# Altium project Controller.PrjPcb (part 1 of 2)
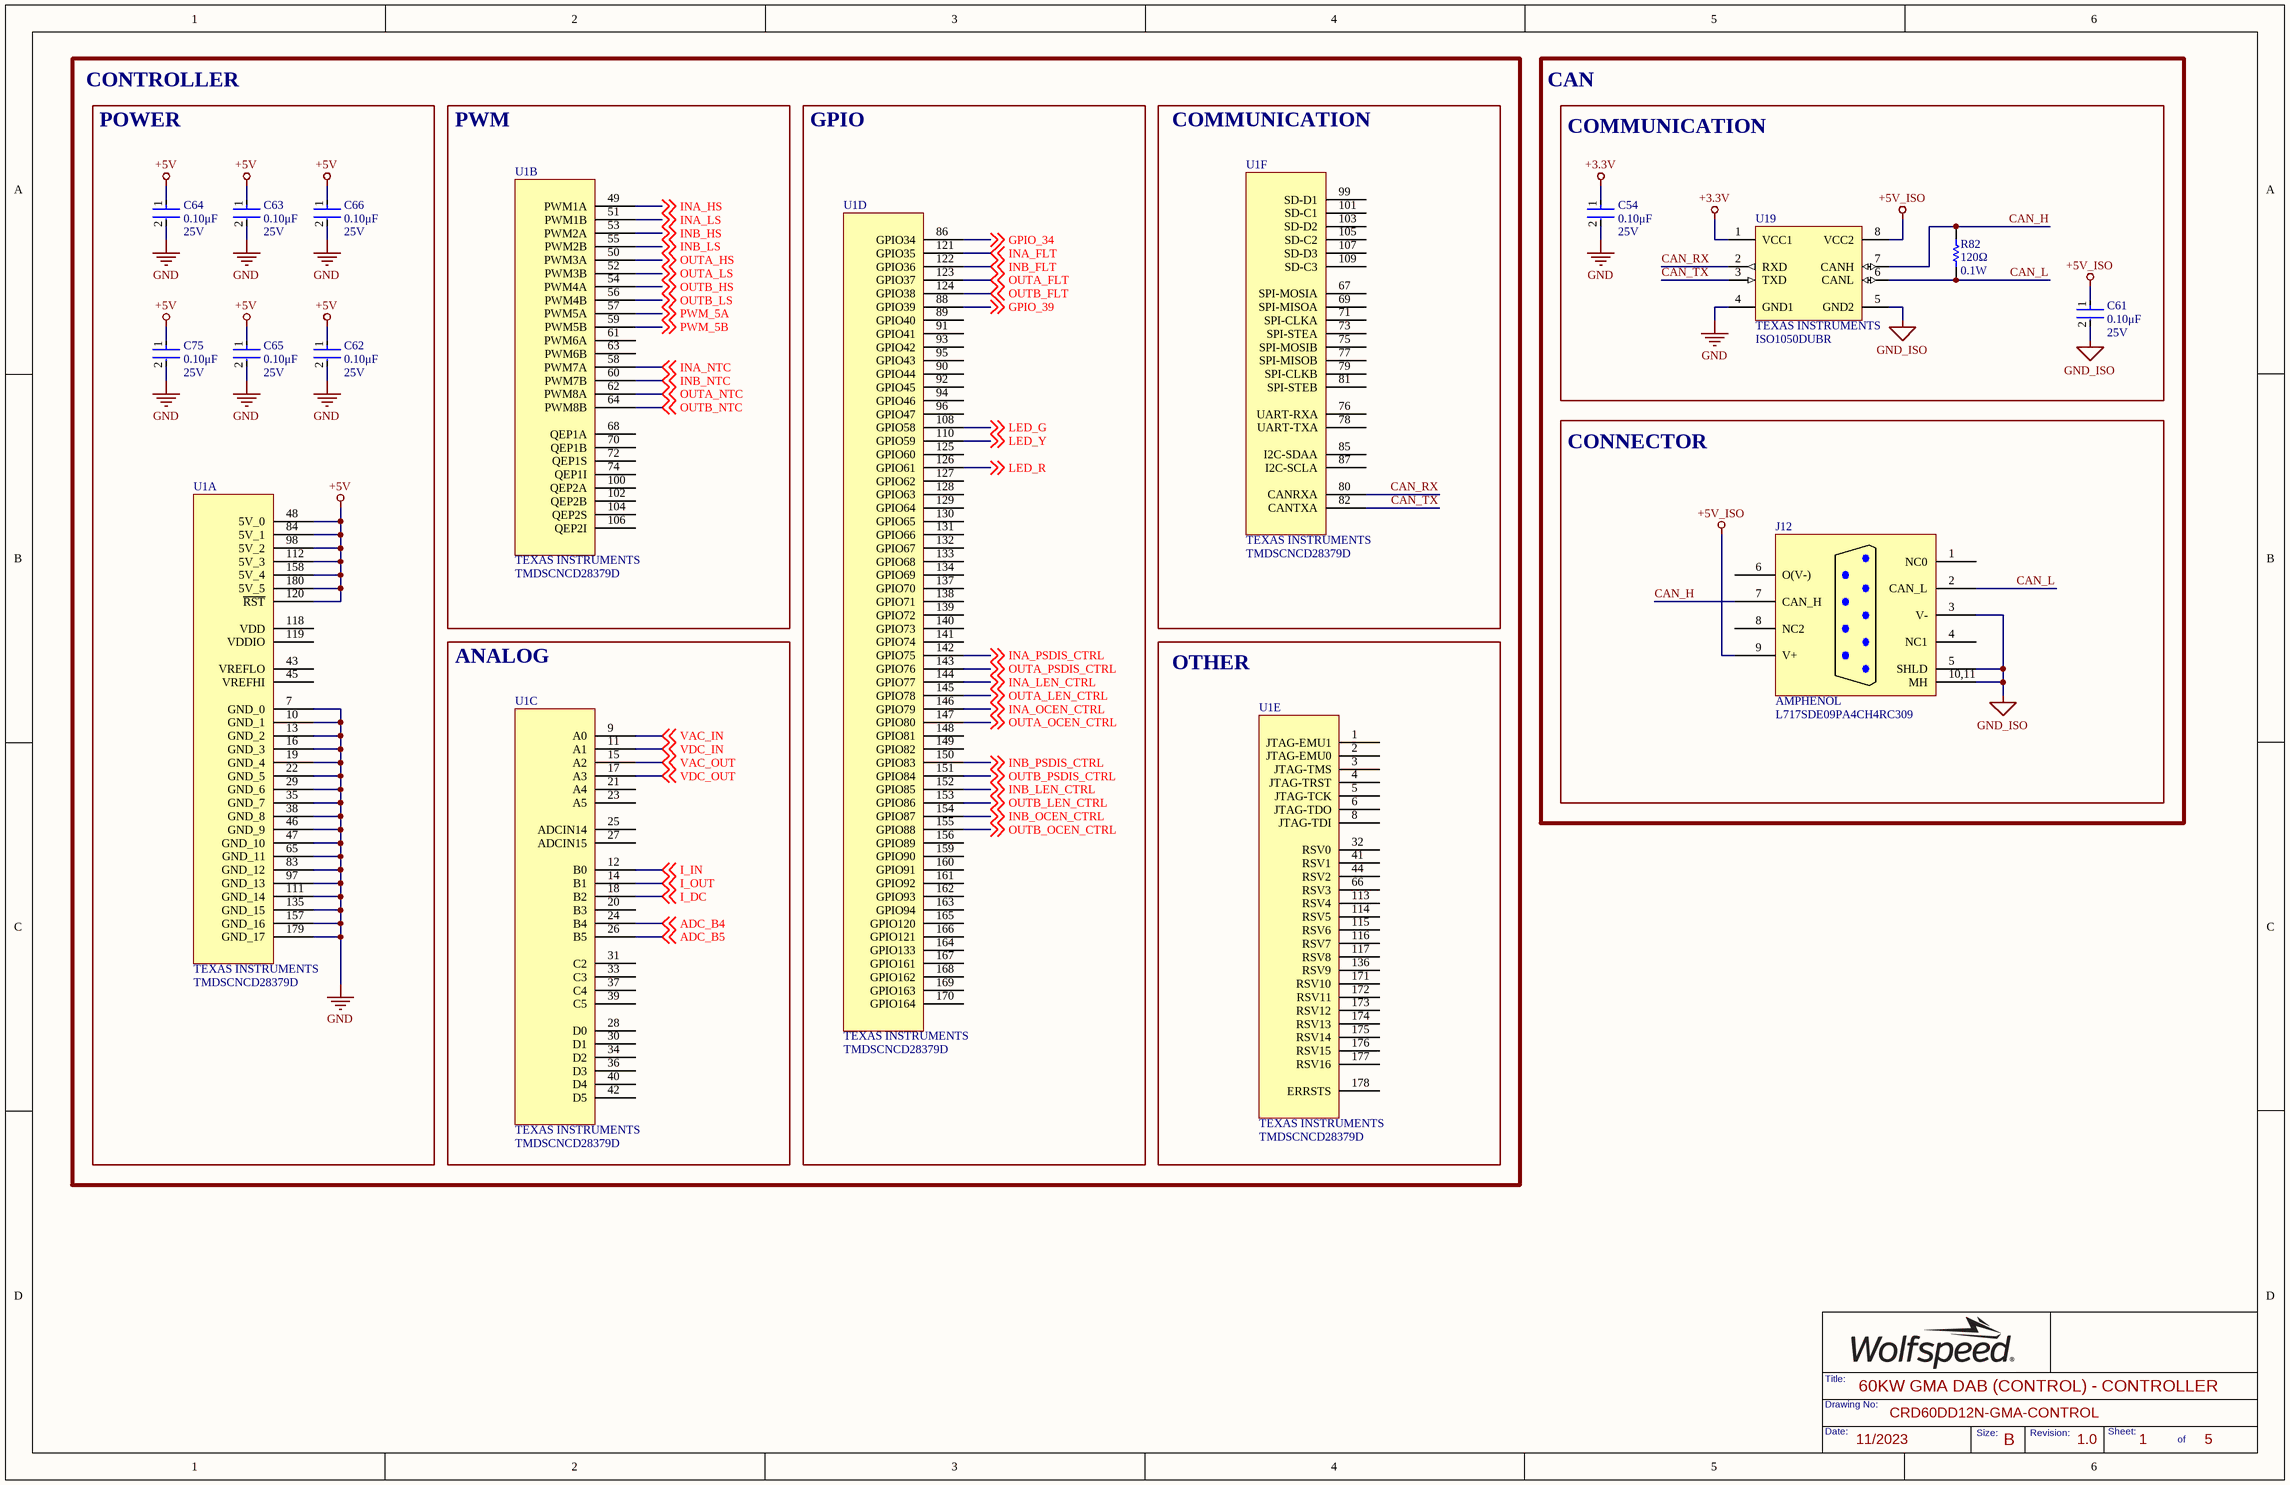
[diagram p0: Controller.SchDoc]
5 sheets, 303 parts. Net scope: global (net labels, ports and power ports of the same name join across sheets).
Board file: Controller.PcbDoc
Sheets:
  Controller.SchDoc
  Voltage Sense.SchDoc
  Gate Drivers.SchDoc
  Current Sense.SchDoc
  Auxiliary Power.SchDoc

## Sheet Controller.SchDoc: 60KW GMA DAB (CONTROL) - CONTROLLER
size 431 x 279 mm; Date: 11/2023; DocumentNumber: CRD60DD12N-GMA-CONTROL; Revision: 1.0; SheetNumber: 1; SheetTotal: 5; SheetSize: B

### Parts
C54  Voltage Rating: 25V  Capacitance: 0.10μF  [FP-C0603C-CF-IPC_B]  (hidden comment: C0603C104K3RACTU)
C61  Voltage Rating: 25V  Capacitance: 0.10μF  [FP-C0603C-CF-IPC_B]  (hidden comment: C0603C104K3RACTU)
C62  Voltage Rating: 25V  Capacitance: 0.10μF  [FP-C0603C-CF-IPC_B]  (hidden comment: C0603C104K3RACTU)
C63  Voltage Rating: 25V  Capacitance: 0.10μF  [FP-C0603C-CF-IPC_B]  (hidden comment: C0603C104K3RACTU)
C64  Voltage Rating: 25V  Capacitance: 0.10μF  [FP-C0603C-CF-IPC_B]  (hidden comment: C0603C104K3RACTU)
C65  Voltage Rating: 25V  Capacitance: 0.10μF  [FP-C0603C-CF-IPC_B]  (hidden comment: C0603C104K3RACTU)
C66  Voltage Rating: 25V  Capacitance: 0.10μF  [FP-C0603C-CF-IPC_B]  (hidden comment: C0603C104K3RACTU)
C75  Voltage Rating: 25V  Capacitance: 0.10μF  [FP-C0603C-CF-IPC_B]  (hidden comment: C0603C104K3RACTU)
J12  Manufacturer: AMPHENOL  [L717SDE09PA4CH4RC309]  (hidden comment: L717SDE09PA4CH4RC309)
R82  Resistance: 120Ω  Max Power Dissipation: 0.1W  [FP-MCR03-IPC_B]  (hidden comment: RC0603JR-07120RL)
U1  Manufacturer: TEXAS INSTRUMENTS  [TMDSCNCD28379D]  (hidden comment: TMDSCNCD28379D)  (parts A,B,C,D,E,F of 6)
U19  ISO1050DUBR  Manufacturer Print: TEXAS INSTRUMENTS  [DUB0008A_M]

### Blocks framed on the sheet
POWER: C62-C66 C75 U1
PWM: U1
GPIO: U1
COMMUNICATION: U1
COMMUNICATION: C54 C61 R82 U19
CONNECTOR: J12
ANALOG: U1
OTHER: U1

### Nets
+3.3V: C54.1 U19.1(VCC1)
+5V: C62.1 C63.1 C64.1 C65.1 C66.1 C75.1 U1.48(5V_0) U1.84(5V_1) U1.98(5V_2) U1.112(5V_3) U1.120(~{RST}) U1.158(5V_4) U1.180(5V_5)
+5V_ISO: C61.1 J12.9(V+) U19.8(VCC2)
GND: C54.2 C62.2 C63.2 C64.2 C65.2 C66.2 C75.2 U1.7(GND_0) U1.10(GND_1) U1.13(GND_2) U1.16(GND_3) U1.19(GND_4) U1.22(GND_5) U1.29(GND_6) U1.35(GND_7) U1.38(GND_8) U1.46(GND_9) U1.47(GND_10) U1.65(GND_11) U1.83(GND_12) U1.97(GND_13) U1.111(GND_14) U1.135(GND_15) U1.157(GND_16) U1.179(GND_17) U19.4(GND1)
GND_ISO: C61.2 J12.3(V-) J12.5(SHLD) J12.10,11(MH) U19.5(GND2)
ADC_B4: U1.24(B4) ; off-sheet ADC_B4
ADC_B5: U1.26(B5) ; off-sheet ADC_B5
CAN_H: J12.7(CAN_H) R82.2 U19.7(CANH)
CAN_L: J12.2(CAN_L) R82.1 U19.6(CANL)
CAN_RX: U1.80(CANRXA) U19.2(RXD)
CAN_TX: U1.82(CANTXA) U19.3(TXD)
GPIO_34: U1.86(GPIO34) ; off-sheet GPIO_34
GPIO_39: U1.88(GPIO39) ; off-sheet GPIO_39
I_DC: U1.18(B2) ; off-sheet I_DC
I_IN: U1.12(B0) ; off-sheet I_IN
I_OUT: U1.14(B1) ; off-sheet I_OUT
INA_FLT: U1.121(GPIO35) ; off-sheet INA_FLT
INA_HS: U1.49(PWM1A) ; off-sheet INA_HS
INA_LEN_CTRL: U1.144(GPIO77) ; off-sheet INA_LEN_CTRL
INA_LS: U1.51(PWM1B) ; off-sheet INA_LS
INA_NTC: U1.58(PWM7A) ; off-sheet INA_NTC
INA_OCEN_CTRL: U1.146(GPIO79) ; off-sheet INA_OCEN_CTRL
INA_PSDIS_CTRL: U1.142(GPIO75) ; off-sheet INA_PSDIS_CTRL
INB_FLT: U1.122(GPIO36) ; off-sheet INB_FLT
INB_HS: U1.53(PWM2A) ; off-sheet INB_HS
INB_LEN_CTRL: U1.152(GPIO85) ; off-sheet INB_LEN_CTRL
INB_LS: U1.55(PWM2B) ; off-sheet INB_LS
INB_NTC: U1.60(PWM7B) ; off-sheet INB_NTC
INB_OCEN_CTRL: U1.154(GPIO87) ; off-sheet INB_OCEN_CTRL
INB_PSDIS_CTRL: U1.150(GPIO83) ; off-sheet INB_PSDIS_CTRL
LED_G: U1.108(GPIO58) ; off-sheet LED_G
LED_R: U1.126(GPIO61) ; off-sheet LED_R
LED_Y: U1.110(GPIO59) ; off-sheet LED_Y
OUTA_FLT: U1.123(GPIO37) ; off-sheet OUTA_FLT
OUTA_HS: U1.50(PWM3A) ; off-sheet OUTA_HS
OUTA_LEN_CTRL: U1.145(GPIO78) ; off-sheet OUTA_LEN_CTRL
OUTA_LS: U1.52(PWM3B) ; off-sheet OUTA_LS
OUTA_NTC: U1.62(PWM8A) ; off-sheet OUTA_NTC
OUTA_OCEN_CTRL: U1.147(GPIO80) ; off-sheet OUTA_OCEN_CTRL
OUTA_PSDIS_CTRL: U1.143(GPIO76) ; off-sheet OUTA_PSDIS_CTRL
OUTB_FLT: U1.124(GPIO38) ; off-sheet OUTB_FLT
OUTB_HS: U1.54(PWM4A) ; off-sheet OUTB_HS
OUTB_LEN_CTRL: U1.153(GPIO86) ; off-sheet OUTB_LEN_CTRL
OUTB_LS: U1.56(PWM4B) ; off-sheet OUTB_LS
OUTB_NTC: U1.64(PWM8B) ; off-sheet OUTB_NTC
OUTB_OCEN_CTRL: U1.155(GPIO88) ; off-sheet OUTB_OCEN_CTRL
OUTB_PSDIS_CTRL: U1.151(GPIO84) ; off-sheet OUTB_PSDIS_CTRL
PWM_5A: U1.57(PWM5A) ; off-sheet PWM_5A
PWM_5B: U1.59(PWM5B) ; off-sheet PWM_5B
VAC_IN: U1.9(A0) ; off-sheet VAC_IN
VAC_OUT: U1.15(A2) ; off-sheet VAC_OUT
VDC_IN: U1.11(A1) ; off-sheet VDC_IN
VDC_OUT: U1.17(A3) ; off-sheet VDC_OUT

Not connected (* = marked no-connect by the designer): J12 1(NC0) 4(NC1) 6(O(V-)) 8(NC2); U1 1(JTAG-EMU1) 2(JTAG-EMU0) 3(JTAG-TMS) 4(JTAG-TRST) 5(JTAG-TCK) 6(JTAG-TDO) 8(JTAG-TDI) 20(B3) 21(A4) 23(A5) 25(ADCIN14) 27(ADCIN15) 28(D0) 30(D1) 31(C2) 32(RSV0) 33(C3) 34(D2) 36(D3) 37(C4) 39(C5) 40(D4) 41(RSV1) 42(D5) 43(VREFLO) 44(RSV2) 45(VREFHI) 61(PWM6A) 63(PWM6B) 66(RSV3) 67(SPI-MOSIA) 68(QEP1A) 69(SPI-MISOA) 70(QEP1B) 71(SPI-CLKA) 72(QEP1S) 73(SPI-STEA) 74(QEP1I) 75(SPI-MOSIB) 76(UART-RXA) 77(SPI-MISOB) 78(UART-TXA) 79(SPI-CLKB) 81(SPI-STEB) 85(I2C-SDAA) 87(I2C-SCLA) 89(GPIO40) 90(GPIO44) 91(GPIO41) 92(GPIO45) 93(GPIO42) 94(GPIO46) 95(GPIO43) 96(GPIO47) 99(SD-D1) 100(QEP2A) 101(SD-C1) 102(QEP2B) 103(SD-D2) 104(QEP2S) 105(SD-C2) 106(QEP2I) 107(SD-D3) 109(SD-C3) 113(RSV4) 114(RSV5) 115(RSV6) 116(RSV7) 117(RSV8) 118(VDD) 119(VDDIO) 125(GPIO60) 127(GPIO62) 128(GPIO63) 129(GPIO64) 130(GPIO65) 131(GPIO66) 132(GPIO67) 133(GPIO68) 134(GPIO69) 136(RSV9) 137(GPIO70) 138(GPIO71) 139(GPIO72) 140(GPIO73) 141(GPIO74) 148(GPIO81) 149(GPIO82) 156(GPIO89) 159(GPIO90) 160(GPIO91) 161(GPIO92) 162(GPIO93) 163(GPIO94) 164(GPIO133) 165(GPIO120) 166(GPIO121) 167(GPIO161) 168(GPIO162) 169(GPIO163) 170(GPIO164) 171(RSV10) 172(RSV11) 173(RSV12) 174(RSV13) 175(RSV14) 176(RSV15) 177(RSV16) 178(ERRSTS)

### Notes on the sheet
- CONTROLLER
- CAN

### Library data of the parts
C54 C61-C66 C75 = CMP-2006-03057-2: CAP CER 0.1UF 25V X7R 0603; Manufacturer: KEMET; Value: 0.10μF; Material: Ceramic; Tolerance: 0.1; Temperature Coefficient: 30ppm/°C; Automotive Grade: Grade 1
J12 = L717SDE09PA4CH4RC309: CONN D-SUB PLUG 9POS R/A SLDR; Number of Terminals/Pins: 9; Connector Type: D-Sub,Plug; Voltage Rating: 250V; Current Rating: 5A; Number of Ports: 1; Pitch: 2.74mm
R82 = RC0603JR-07120RL: RES SMD 120 OHM 5% 1/10W 0603; Manufacturer: YAGEO; Voltage Rating (DC): 50V; Temperature Coefficient: 100ppm/°C; Power Rating: 100mW; Value: 120Ω
U1 = TMDSCNCD28379D: CONTROLCARD TMS320F28379D EVAL; Evaluation Kit: Yes
U19 = ISO1050DUBR: IC TXRX/ISO HALF 1/1 8SOP; Rating: Catalog; Eco-Plan: Green (RoHS & no Sb/Br); Isolated: Yes; Drivers Per Package: 1; SubFamily: CAN

## Sheet Voltage Sense.SchDoc: 60KW GMA DAB (CONTROL) - VOLTAGE SENSE
size 431 x 279 mm; Date: 11/2023; Revision: 1.0; SheetNumber: 2; SheetTotal: 5; SheetSize: B; DrawingNumber: CRD60DD12N-GMA-CONTROL
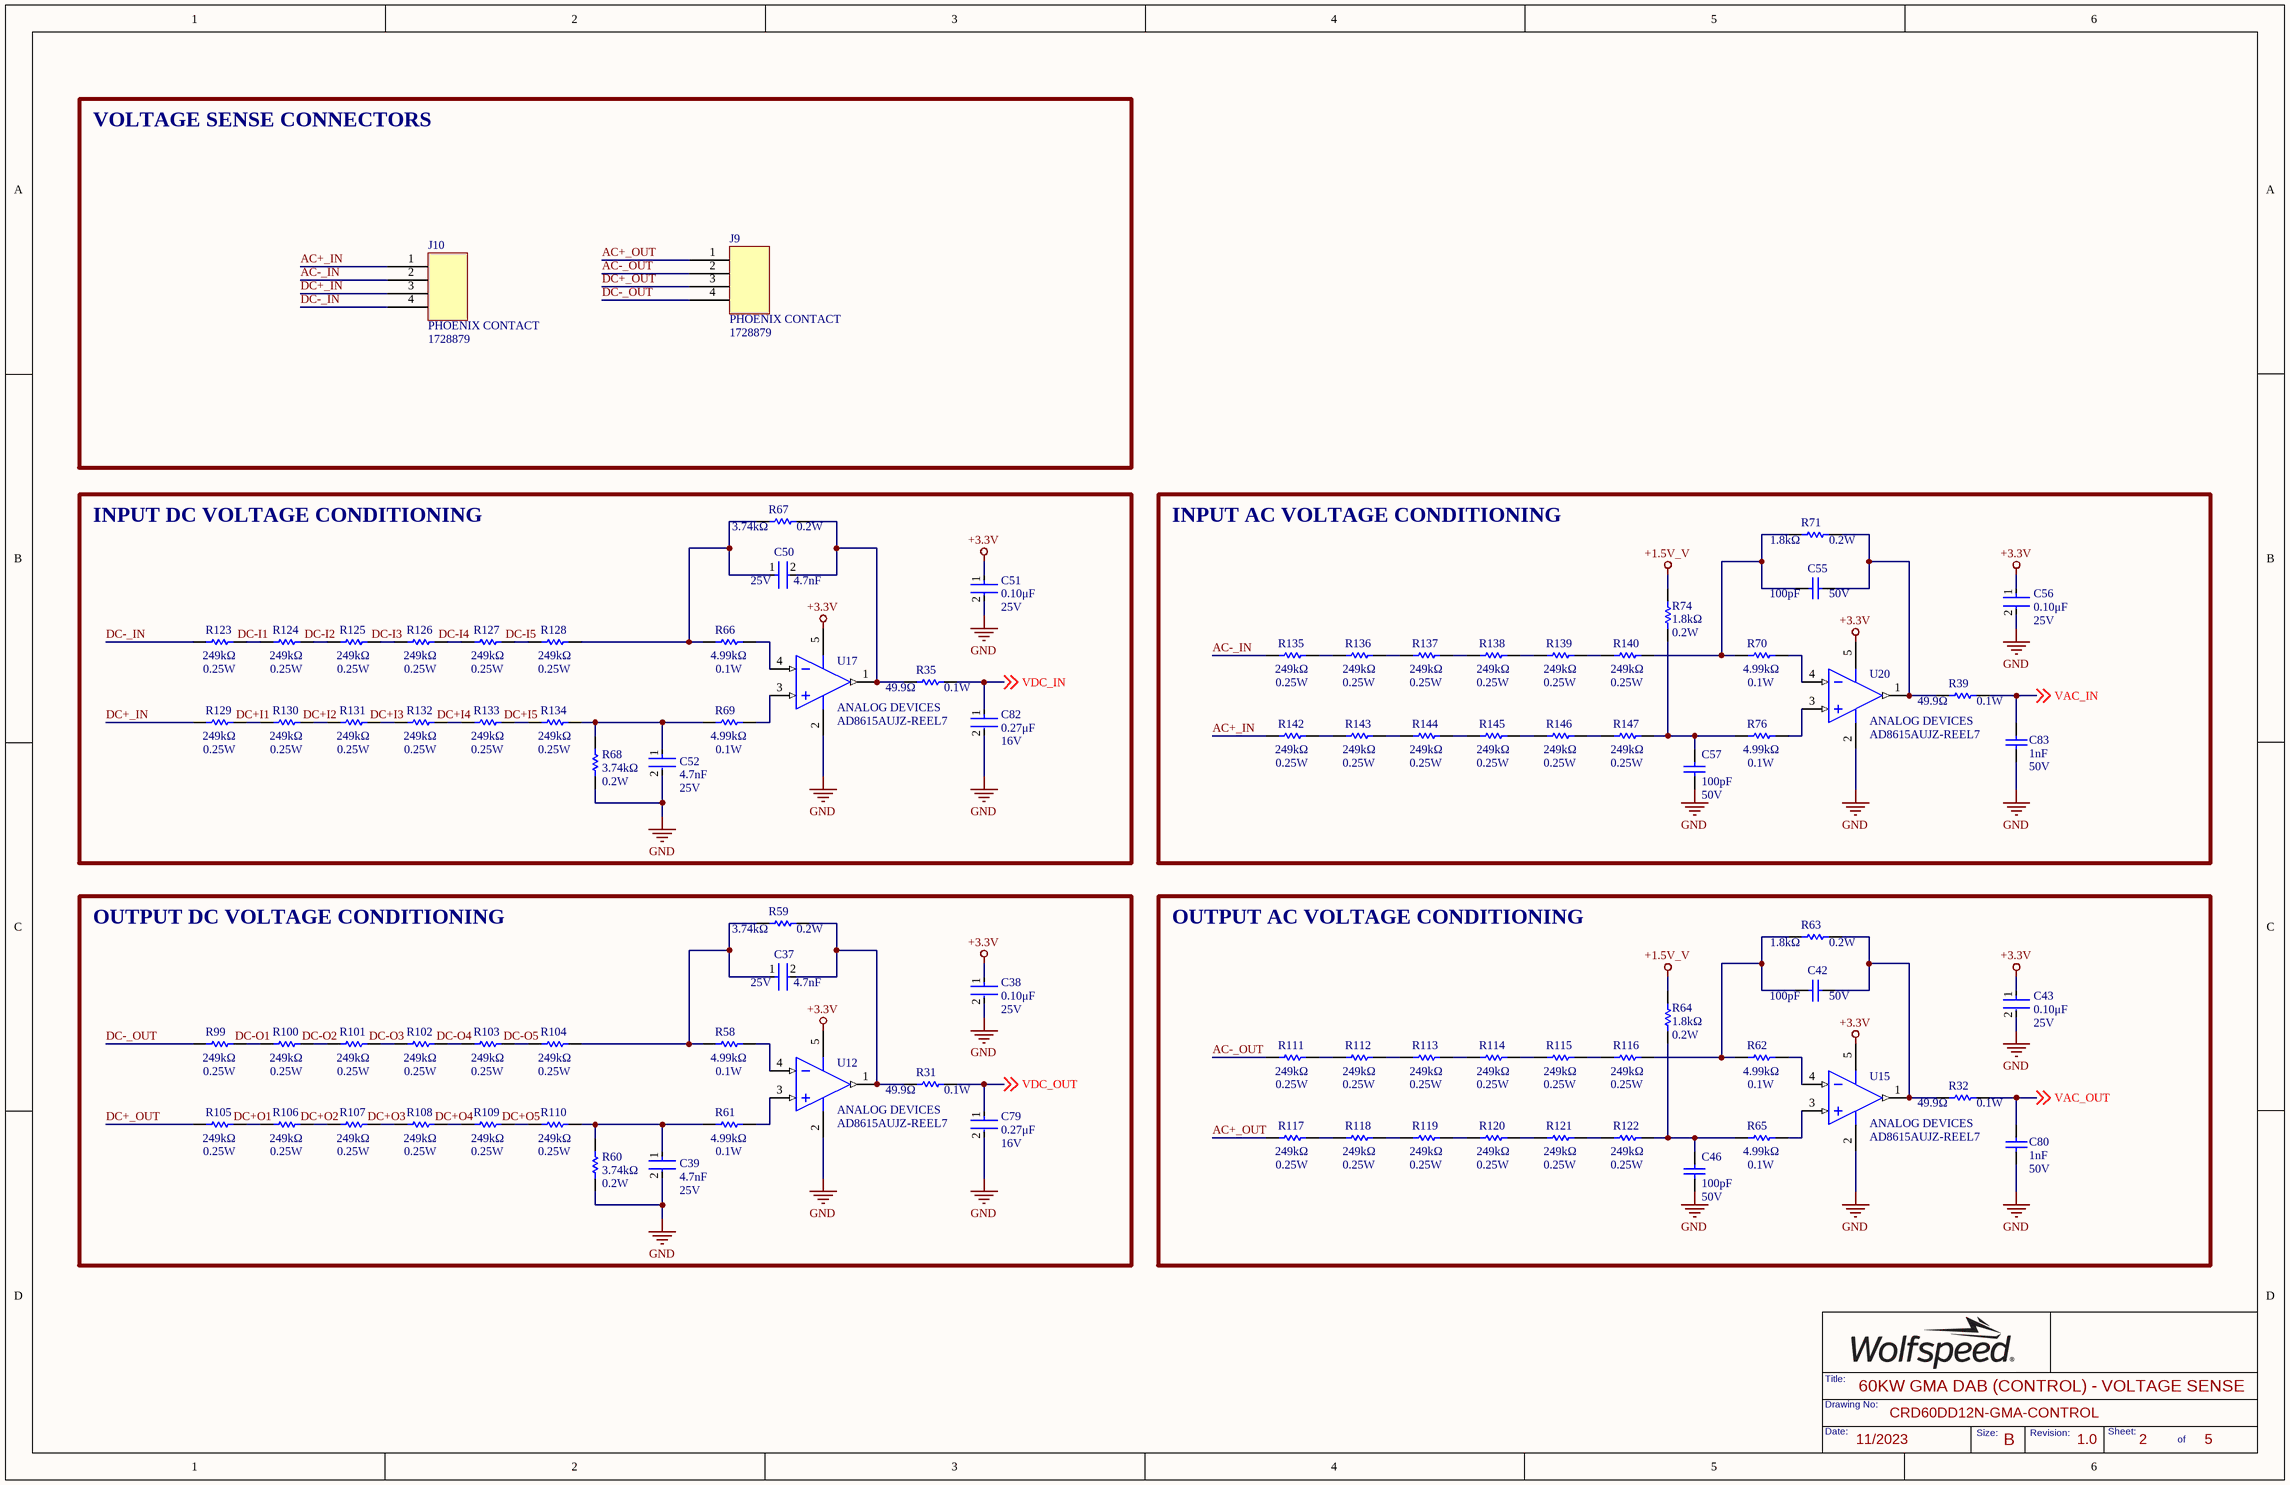
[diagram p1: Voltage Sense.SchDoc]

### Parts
C37  Voltage Rating: 25V  Capacitance: 4.7nF  [FP-C0603C-CF-IPC_B]  (hidden comment: C0603C472K3RAC7867)
C38  Voltage Rating: 25V  Capacitance: 0.10μF  [FP-C0603C-CF-IPC_B]  (hidden comment: C0603C104K3RACTU)
C39  Voltage Rating: 25V  Capacitance: 4.7nF  [FP-C0603C-CF-IPC_B]  (hidden comment: C0603C472K3RAC7867)
C42  value 100pF  Voltage Rating: 50V  [FP-C0603C-CF-IPC_B]  (hidden comment: CC0603KRX7R9BB101)
C43  Voltage Rating: 25V  Capacitance: 0.10μF  [FP-C0603C-CF-IPC_B]  (hidden comment: C0603C104K3RACTU)
C46  value 100pF  Voltage Rating: 50V  [FP-C0603C-CF-IPC_B]  (hidden comment: CC0603KRX7R9BB101)
C50  Voltage Rating: 25V  Capacitance: 4.7nF  [FP-C0603C-CF-IPC_B]  (hidden comment: C0603C472K3RAC7867)
C51  Voltage Rating: 25V  Capacitance: 0.10μF  [FP-C0603C-CF-IPC_B]  (hidden comment: C0603C104K3RACTU)
C52  Voltage Rating: 25V  Capacitance: 4.7nF  [FP-C0603C-CF-IPC_B]  (hidden comment: C0603C472K3RAC7867)
C55  value 100pF  Voltage Rating: 50V  [FP-C0603C-CF-IPC_B]  (hidden comment: CC0603KRX7R9BB101)
C56  Voltage Rating: 25V  Capacitance: 0.10μF  [FP-C0603C-CF-IPC_B]  (hidden comment: C0603C104K3RACTU)
C57  value 100pF  Voltage Rating: 50V  [FP-C0603C-CF-IPC_B]  (hidden comment: CC0603KRX7R9BB101)
C79  Voltage Rating (DC): 16V  Capacitance: 0.27μF  [FP-GCM188-0_1-IPC_A]  (hidden comment: GCM188R71C274KA37D)
C80  value 1nF  Voltage Rating: 50V  [FP-C0603C-CF-IPC_B]  (hidden comment: GRM1885C1H102GA01D)
C82  Voltage Rating (DC): 16V  Capacitance: 0.27μF  [FP-GCM188-0_1-IPC_A]  (hidden comment: GCM188R71C274KA37D)
C83  value 1nF  Voltage Rating: 50V  [FP-C0603C-CF-IPC_B]  (hidden comment: GRM1885C1H102GA01D)
J9  1728879  Manufacturer: PHOENIX CONTACT  [1728879]
J10  1728879  Manufacturer: PHOENIX CONTACT  [1728879]
R31  Resistance: 49.9Ω  Power Rating: 0.1W  [FP-MCR03-IPC_B]  (hidden comment: ERJ-3EKF49R9V)
R32  Resistance: 49.9Ω  Power Rating: 0.1W  [FP-MCR03-IPC_B]  (hidden comment: ERJ-3EKF49R9V)
R35  Resistance: 49.9Ω  Power Rating: 0.1W  [FP-MCR03-IPC_B]  (hidden comment: ERJ-3EKF49R9V)
R39  Resistance: 49.9Ω  Power Rating: 0.1W  [FP-MCR03-IPC_B]  (hidden comment: ERJ-3EKF49R9V)
R58  Power Rating: 0.1W  Resistance: 4.99kΩ  [FP-MCR03-IPC_B]  (hidden comment: RC0603FR-074K99L)
R59  Max Power Dissipation: 0.2W  Resistance: 3.74kΩ  [FP-MCR03-IPC_B]  (hidden comment: ERJ-PB3B3741V)
R60  Max Power Dissipation: 0.2W  Resistance: 3.74kΩ  [FP-MCR03-IPC_B]  (hidden comment: ERJ-PB3B3741V)
R61  Power Rating: 0.1W  Resistance: 4.99kΩ  [FP-MCR03-IPC_B]  (hidden comment: RC0603FR-074K99L)
R62  Power Rating: 0.1W  Resistance: 4.99kΩ  [FP-MCR03-IPC_B]  (hidden comment: RC0603FR-074K99L)
R63  Resistance: 1.8kΩ  Max Power Dissipation: 0.2W  [FP-MCR03-IPC_B]  (hidden comment: ERJ-PB3B1801V)
R64  Resistance: 1.8kΩ  Max Power Dissipation: 0.2W  [FP-MCR03-IPC_B]  (hidden comment: ERJ-PB3B1801V)
R65  Power Rating: 0.1W  Resistance: 4.99kΩ  [FP-MCR03-IPC_B]  (hidden comment: RC0603FR-074K99L)
R66  Power Rating: 0.1W  Resistance: 4.99kΩ  [FP-MCR03-IPC_B]  (hidden comment: RC0603FR-074K99L)
R67  Max Power Dissipation: 0.2W  Resistance: 3.74kΩ  [FP-MCR03-IPC_B]  (hidden comment: ERJ-PB3B3741V)
R68  Max Power Dissipation: 0.2W  Resistance: 3.74kΩ  [FP-MCR03-IPC_B]  (hidden comment: ERJ-PB3B3741V)
R69  Power Rating: 0.1W  Resistance: 4.99kΩ  [FP-MCR03-IPC_B]  (hidden comment: RC0603FR-074K99L)
R70  Power Rating: 0.1W  Resistance: 4.99kΩ  [FP-MCR03-IPC_B]  (hidden comment: RC0603FR-074K99L)
R71  Resistance: 1.8kΩ  Max Power Dissipation: 0.2W  [FP-MCR03-IPC_B]  (hidden comment: ERJ-PB3B1801V)
R74  Resistance: 1.8kΩ  Max Power Dissipation: 0.2W  [FP-MCR03-IPC_B]  (hidden comment: ERJ-PB3B1801V)
R76  Power Rating: 0.1W  Resistance: 4.99kΩ  [FP-MCR03-IPC_B]  (hidden comment: RC0603FR-074K99L)
R99  Resistance: 249kΩ  Power: 0.25W  [RESC3216X65X50NL15T25]  (hidden comment: TNPW1206249KBEEA)
R100  Resistance: 249kΩ  Power: 0.25W  [RESC3216X65X50NL15T25]  (hidden comment: TNPW1206249KBEEA)
R101  Resistance: 249kΩ  Power: 0.25W  [RESC3216X65X50NL15T25]  (hidden comment: TNPW1206249KBEEA)
R102  Resistance: 249kΩ  Power: 0.25W  [RESC3216X65X50NL15T25]  (hidden comment: TNPW1206249KBEEA)
R103  Resistance: 249kΩ  Power: 0.25W  [RESC3216X65X50NL15T25]  (hidden comment: TNPW1206249KBEEA)
R104  Resistance: 249kΩ  Power: 0.25W  [RESC3216X65X50NL15T25]  (hidden comment: TNPW1206249KBEEA)
R105  Resistance: 249kΩ  Power: 0.25W  [RESC3216X65X50NL15T25]  (hidden comment: TNPW1206249KBEEA)
R106  Resistance: 249kΩ  Power: 0.25W  [RESC3216X65X50NL15T25]  (hidden comment: TNPW1206249KBEEA)
R107  Resistance: 249kΩ  Power: 0.25W  [RESC3216X65X50NL15T25]  (hidden comment: TNPW1206249KBEEA)
R108  Resistance: 249kΩ  Power: 0.25W  [RESC3216X65X50NL15T25]  (hidden comment: TNPW1206249KBEEA)
R109  Resistance: 249kΩ  Power: 0.25W  [RESC3216X65X50NL15T25]  (hidden comment: TNPW1206249KBEEA)
R110  Resistance: 249kΩ  Power: 0.25W  [RESC3216X65X50NL15T25]  (hidden comment: TNPW1206249KBEEA)
R111  Resistance: 249kΩ  Power: 0.25W  [RESC3216X65X50NL15T25]  (hidden comment: TNPW1206249KBEEA)
R112  Resistance: 249kΩ  Power: 0.25W  [RESC3216X65X50NL15T25]  (hidden comment: TNPW1206249KBEEA)
R113  Resistance: 249kΩ  Power: 0.25W  [RESC3216X65X50NL15T25]  (hidden comment: TNPW1206249KBEEA)
R114  Resistance: 249kΩ  Power: 0.25W  [RESC3216X65X50NL15T25]  (hidden comment: TNPW1206249KBEEA)
R115  Resistance: 249kΩ  Power: 0.25W  [RESC3216X65X50NL15T25]  (hidden comment: TNPW1206249KBEEA)
R116  Resistance: 249kΩ  Power: 0.25W  [RESC3216X65X50NL15T25]  (hidden comment: TNPW1206249KBEEA)
R117  Resistance: 249kΩ  Power: 0.25W  [RESC3216X65X50NL15T25]  (hidden comment: TNPW1206249KBEEA)
R118  Resistance: 249kΩ  Power: 0.25W  [RESC3216X65X50NL15T25]  (hidden comment: TNPW1206249KBEEA)
R119  Resistance: 249kΩ  Power: 0.25W  [RESC3216X65X50NL15T25]  (hidden comment: TNPW1206249KBEEA)
R120  Resistance: 249kΩ  Power: 0.25W  [RESC3216X65X50NL15T25]  (hidden comment: TNPW1206249KBEEA)
R121  Resistance: 249kΩ  Power: 0.25W  [RESC3216X65X50NL15T25]  (hidden comment: TNPW1206249KBEEA)
R122  Resistance: 249kΩ  Power: 0.25W  [RESC3216X65X50NL15T25]  (hidden comment: TNPW1206249KBEEA)
R123  Resistance: 249kΩ  Power: 0.25W  [RESC3216X65X50NL15T25]  (hidden comment: TNPW1206249KBEEA)
R124  Resistance: 249kΩ  Power: 0.25W  [RESC3216X65X50NL15T25]  (hidden comment: TNPW1206249KBEEA)
R125  Resistance: 249kΩ  Power: 0.25W  [RESC3216X65X50NL15T25]  (hidden comment: TNPW1206249KBEEA)
R126  Resistance: 249kΩ  Power: 0.25W  [RESC3216X65X50NL15T25]  (hidden comment: TNPW1206249KBEEA)
R127  Resistance: 249kΩ  Power: 0.25W  [RESC3216X65X50NL15T25]  (hidden comment: TNPW1206249KBEEA)
R128  Resistance: 249kΩ  Power: 0.25W  [RESC3216X65X50NL15T25]  (hidden comment: TNPW1206249KBEEA)
R129  Resistance: 249kΩ  Power: 0.25W  [RESC3216X65X50NL15T25]  (hidden comment: TNPW1206249KBEEA)
R130  Resistance: 249kΩ  Power: 0.25W  [RESC3216X65X50NL15T25]  (hidden comment: TNPW1206249KBEEA)
R131  Resistance: 249kΩ  Power: 0.25W  [RESC3216X65X50NL15T25]  (hidden comment: TNPW1206249KBEEA)
R132  Resistance: 249kΩ  Power: 0.25W  [RESC3216X65X50NL15T25]  (hidden comment: TNPW1206249KBEEA)
R133  Resistance: 249kΩ  Power: 0.25W  [RESC3216X65X50NL15T25]  (hidden comment: TNPW1206249KBEEA)
R134  Resistance: 249kΩ  Power: 0.25W  [RESC3216X65X50NL15T25]  (hidden comment: TNPW1206249KBEEA)
R135  Resistance: 249kΩ  Power: 0.25W  [RESC3216X65X50NL15T25]  (hidden comment: TNPW1206249KBEEA)
R136  Resistance: 249kΩ  Power: 0.25W  [RESC3216X65X50NL15T25]  (hidden comment: TNPW1206249KBEEA)
R137  Resistance: 249kΩ  Power: 0.25W  [RESC3216X65X50NL15T25]  (hidden comment: TNPW1206249KBEEA)
R138  Resistance: 249kΩ  Power: 0.25W  [RESC3216X65X50NL15T25]  (hidden comment: TNPW1206249KBEEA)
R139  Resistance: 249kΩ  Power: 0.25W  [RESC3216X65X50NL15T25]  (hidden comment: TNPW1206249KBEEA)
R140  Resistance: 249kΩ  Power: 0.25W  [RESC3216X65X50NL15T25]  (hidden comment: TNPW1206249KBEEA)
R142  Resistance: 249kΩ  Power: 0.25W  [RESC3216X65X50NL15T25]  (hidden comment: TNPW1206249KBEEA)
R143  Resistance: 249kΩ  Power: 0.25W  [RESC3216X65X50NL15T25]  (hidden comment: TNPW1206249KBEEA)
R144  Resistance: 249kΩ  Power: 0.25W  [RESC3216X65X50NL15T25]  (hidden comment: TNPW1206249KBEEA)
R145  Resistance: 249kΩ  Power: 0.25W  [RESC3216X65X50NL15T25]  (hidden comment: TNPW1206249KBEEA)
R146  Resistance: 249kΩ  Power: 0.25W  [RESC3216X65X50NL15T25]  (hidden comment: TNPW1206249KBEEA)
R147  Resistance: 249kΩ  Power: 0.25W  [RESC3216X65X50NL15T25]  (hidden comment: TNPW1206249KBEEA)
U12  Manufacturer: ANALOG DEVICES  [ADI-UJ-5_M]  (hidden comment: AD8615AUJZ-REEL7)
U15  Manufacturer: ANALOG DEVICES  [ADI-UJ-5_M]  (hidden comment: AD8615AUJZ-REEL7)
U17  Manufacturer: ANALOG DEVICES  [ADI-UJ-5_M]  (hidden comment: AD8615AUJZ-REEL7)
U20  Manufacturer: ANALOG DEVICES  [ADI-UJ-5_M]  (hidden comment: AD8615AUJZ-REEL7)

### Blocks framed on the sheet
VOLTAGE SENSE CONNECTORS: J9 J10
INPUT DC VOLTAGE CONDITIONING: C50-C52 C82 R35 R66-R69 R123-R134 U17
INPUT AC VOLTAGE CONDITIONING: C55-C57 C83 R39 R70 R71 R74 R76 R135-R140 R142-R147 U20
OUTPUT DC VOLTAGE CONDITIONING: C37-C39 C79 R31 R58-R61 R99-R110 U12
OUTPUT AC VOLTAGE CONDITIONING: C42 C43 C46 C80 R32 R62-R65 R111-R122 U15

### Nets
+1.5V_V: R64.2 R74.2
+3.3V: C38.1 C43.1 C51.1 C56.1 U12.5(+V) U15.5(+V) U17.5(+V) U20.5(+V)
GND: C38.2 C39.2 C43.2 C46.2 C51.2 C52.2 C56.2 C57.2 C79.2 C80.2 C82.2 C83.2 R60.1 R68.1 U12.2(-V) U15.2(-V) U17.2(-V) U20.2(-V)
AC+_IN: J10.1 R142.1
AC+_OUT: J9.1 R117.1
AC-_IN: J10.2 R135.1
AC-_OUT: J9.2 R111.1
DC+_IN: J10.3 R129.1
DC+_OUT: J9.3 R105.1
DC+I1: R129.2 R130.1
DC+I2: R130.2 R131.1
DC+I3: R131.2 R132.1
DC+I4: R132.2 R133.1
DC+I5: R133.2 R134.1
DC+O1: R105.2 R106.1
DC+O2: R106.2 R107.1
DC+O3: R107.2 R108.1
DC+O4: R108.2 R109.1
DC+O5: R109.2 R110.1
DC-_IN: J10.4 R123.1
DC-_OUT: J9.4 R99.1
DC-I1: R123.2 R124.1
DC-I2: R124.2 R125.1
DC-I3: R125.2 R126.1
DC-I4: R126.2 R127.1
DC-I5: R127.2 R128.1
DC-O1: R99.2 R100.1
DC-O2: R100.2 R101.1
DC-O3: R101.2 R102.1
DC-O4: R102.2 R103.1
DC-O5: R103.2 R104.1
VAC_IN: C83.1 R39.2 ; off-sheet VAC_IN
VAC_OUT: C80.1 R32.2 ; off-sheet VAC_OUT
VDC_IN: C82.1 R35.2 ; off-sheet VDC_IN
VDC_OUT: C79.1 R31.2 ; off-sheet VDC_OUT
NetC37_1: C37.1 R58.1 R59.1 R104.2
NetC37_2: C37.2 R31.1 R59.2 U12.1(OUT)
NetC39_1: C39.1 R60.2 R61.1 R110.2
NetC42_1: C42.1 R62.1 R63.2 R116.2
NetC42_2: C42.2 R32.1 R63.1 U15.1(OUT)
NetC46_1: C46.1 R64.1 R65.1 R122.2
NetC50_1: C50.1 R66.1 R67.1 R128.2
NetC50_2: C50.2 R35.1 R67.2 U17.1(OUT)
NetC52_1: C52.1 R68.2 R69.1 R134.2
NetC55_1: C55.1 R70.1 R71.2 R140.2
NetC55_2: C55.2 R39.1 R71.1 U20.1(OUT)
NetC57_1: C57.1 R74.1 R76.1 R147.2
NetR58_2: R58.2 U12.4(-IN)
NetR61_2: R61.2 U12.3(+IN)
NetR62_2: R62.2 U15.4(-IN)
NetR65_2: R65.2 U15.3(+IN)
NetR66_2: R66.2 U17.4(-IN)
NetR69_2: R69.2 U17.3(+IN)
NetR70_2: R70.2 U20.4(-IN)
NetR76_2: R76.2 U20.3(+IN)
NetR111_2: R111.2 R112.1
NetR112_2: R112.2 R113.1
NetR113_2: R113.2 R114.1
NetR114_2: R114.2 R115.1
NetR115_2: R115.2 R116.1
NetR117_2: R117.2 R118.1
NetR118_2: R118.2 R119.1
NetR119_2: R119.2 R120.1
NetR120_2: R120.2 R121.1
NetR121_2: R121.2 R122.1
NetR135_2: R135.2 R136.1
NetR136_2: R136.2 R137.1
NetR137_2: R137.2 R138.1
NetR138_2: R138.2 R139.1
NetR139_2: R139.2 R140.1
NetR142_2: R142.2 R143.1
NetR143_2: R143.2 R144.1
NetR144_2: R144.2 R145.1
NetR145_2: R145.2 R146.1
NetR146_2: R146.2 R147.1

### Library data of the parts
C37 C39 C50 C52 = C0603C472K3RAC7867: CAP CER 4700PF 25V 10% X7R 0603; Manufacturer: KEMET; Manufacturer Part Number: C0603C472K3RACTU; Dielectric Material: Ceramic; Value: 4.7nF
C38 C43 C51 C56 = CMP-2006-03057-2: as C54 on sheet Controller
C42 C46 C55 C57 = CMP-001-00096-9: CAP CER 100PF 50V X7R 0603; Manufacturer: YAGEO; Tolerance: 10%; Capacitor Type: Ceramic
C79 C82 = CMP-06035-043171-1: CAP CER 0.27UF 16V X7R 0603; Manufacturer: MURATA; Tolerance: 10%; Value: 0.27μF
C80 C83 = CMP-001-00098-12: CAP CER 1000PF 50V C0G/NP0 0603; Manufacturer: KEMET; Manufacturer Part Number: C0603C102G5GAC7867; Capacitor Type: Ceramic; Tolerance: 2%; Temperature Coefficient: C0G
J9 J10 = 1728879: TERM BLOCK HDR 4POS 90DEG 7.62MM
R31 R32 R35 R39 = ERJ-3EKF49R9V: RES SMD 49.9 OHM 1% 1/10W 0603; Manufacturer: PANASONIC; Temperature Coefficient: 100ppm/°C; Voltage Rating: 75V; Max Power Dissipation: 100mW; Voltage Rating (DC): 50V; Working Voltage: 6V; Value: 49.9Ω
R58 R61 R62 R65 R66 R69 R70 R76 = RC0603FR-074K99L: RES 4.99K OHM 1% 1/10W 0603; Manufacturer: YAGEO; Voltage Rating: 75V; Temperature Coefficient: 100ppm/°C; Voltage Rating (DC): 50V; Value: 4.99kΩ
R59 R60 R67 R68 = ERJ-PB3B3741V: RES SMD 3.74K OHM 0.1% 1/5W 0603; Manufacturer: PANASONIC; Temperature Coefficient: 50ppm/°C; Value: 3.74kΩ
R63 R64 R71 R74 = ERJ-PB3B1801V: RES SMD 1.8K OHM 0.1% 1/5W 0603; Manufacturer: PANASONIC; Temperature Coefficient: 50ppm/°C; Value: 1.8kΩ
R99-R140 R142-R147 = CMP-2003-04604-1: RES 249K OHM 0.1% 1/4W 1206; Manufacturer: VISHAY DALE; Value: 249kΩ
U12 U15 U17 U20 = CMP-0384-02059-2: IC OPAMP GP 1 CIRCUIT TSOT23-5; Generic Part Number: AD8615; Iq/Amp: 1.7mA; V Span Max: 6V; Amplifiers Per Package: 1; Small Signal Bandwidth: 23MHz; Input Offset Voltage: 80uV; V Span Min: 2.7V; Slew Rate: 12V/us; Input Bias Current: 200fA

## Sheet Gate Drivers.SchDoc: 60KW GMA DAB (CONTROL) - GATE DRIVERS
size 431 x 279 mm; Date: 11/2023; Revision: 1.0; SheetNumber: 3; SheetTotal: 5; SheetSize: B; DrawingNumber: CRD60DD12N-GMA-CONTROL
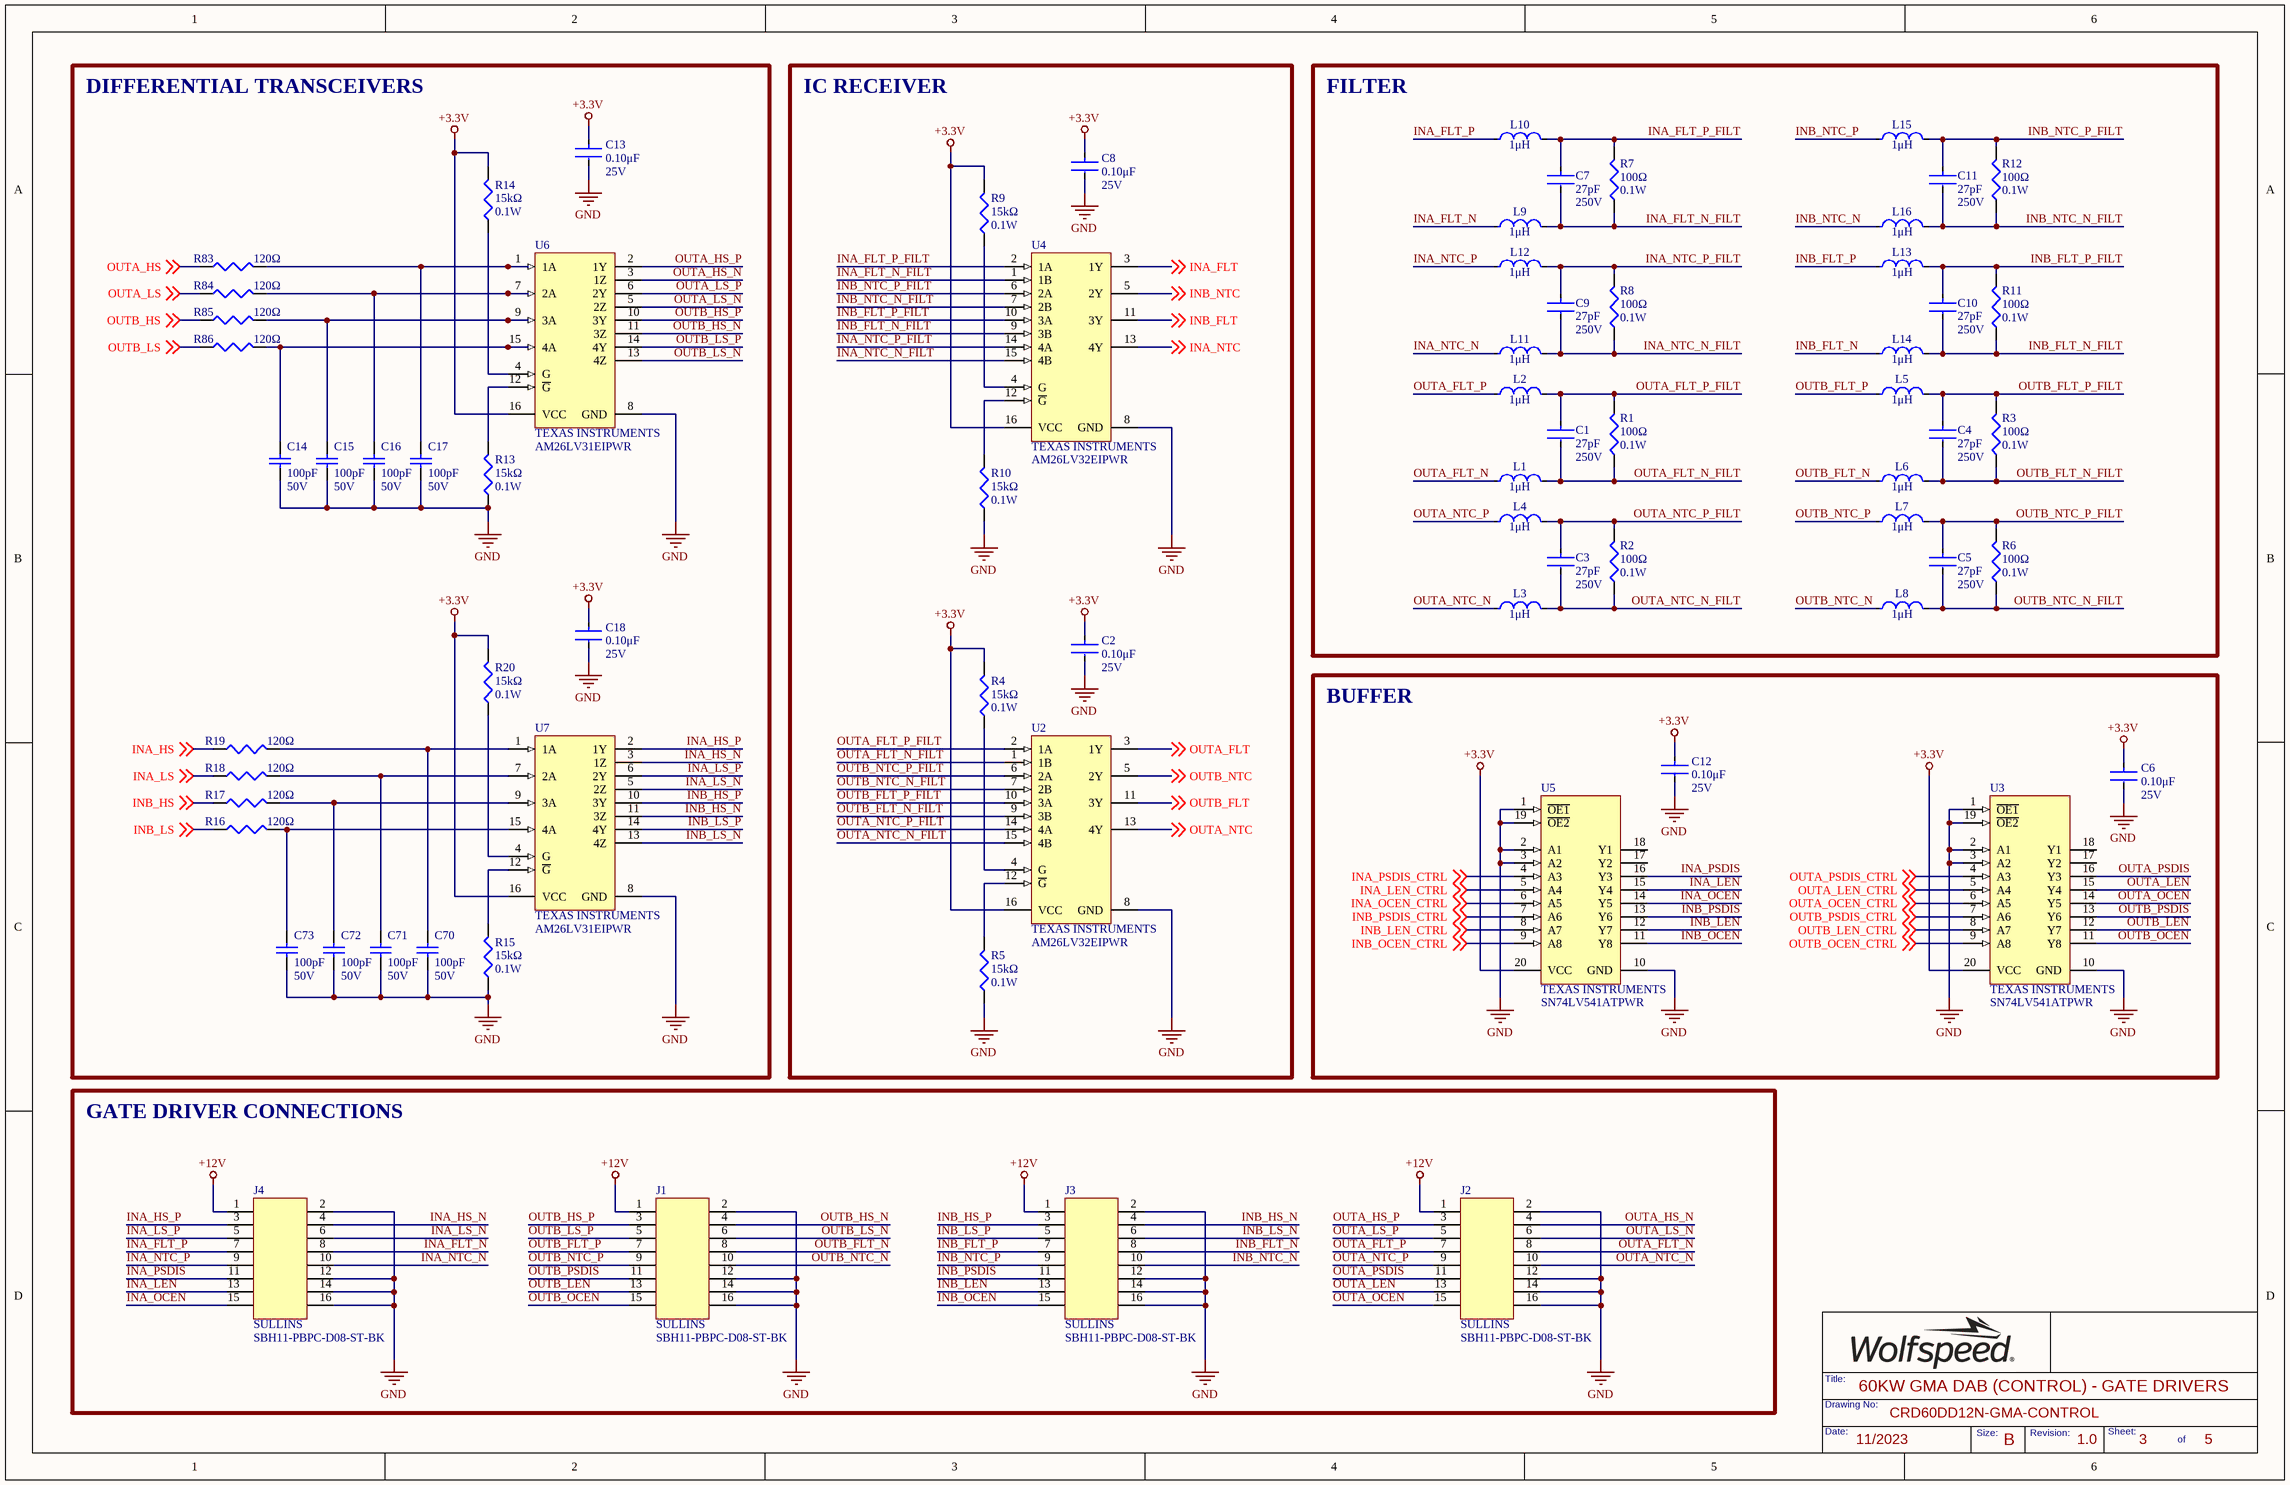
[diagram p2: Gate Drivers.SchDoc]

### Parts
C1  value 27pF  Voltage Rating: 250V  [FP-CBR06C-MFG]  (hidden comment: CBR06C270FAGAC)
C2  Voltage Rating: 25V  Capacitance: 0.10μF  [FP-C0603C-CF-IPC_B]  (hidden comment: C0603C104K3RACTU)
C3  value 27pF  Voltage Rating: 250V  [FP-CBR06C-MFG]  (hidden comment: CBR06C270FAGAC)
C4  value 27pF  Voltage Rating: 250V  [FP-CBR06C-MFG]  (hidden comment: CBR06C270FAGAC)
C5  value 27pF  Voltage Rating: 250V  [FP-CBR06C-MFG]  (hidden comment: CBR06C270FAGAC)
C6  Voltage Rating: 25V  Capacitance: 0.10μF  [FP-C0603C-CF-IPC_B]  (hidden comment: C0603C104K3RACTU)
C7  value 27pF  Voltage Rating: 250V  [FP-CBR06C-MFG]  (hidden comment: CBR06C270FAGAC)
C8  Voltage Rating: 25V  Capacitance: 0.10μF  [FP-C0603C-CF-IPC_B]  (hidden comment: C0603C104K3RACTU)
C9  value 27pF  Voltage Rating: 250V  [FP-CBR06C-MFG]  (hidden comment: CBR06C270FAGAC)
C10  value 27pF  Voltage Rating: 250V  [FP-CBR06C-MFG]  (hidden comment: CBR06C270FAGAC)
C11  value 27pF  Voltage Rating: 250V  [FP-CBR06C-MFG]  (hidden comment: CBR06C270FAGAC)
C12  Voltage Rating: 25V  Capacitance: 0.10μF  [FP-C0603C-CF-IPC_B]  (hidden comment: C0603C104K3RACTU)
C13  Voltage Rating: 25V  Capacitance: 0.10μF  [FP-C0603C-CF-IPC_B]  (hidden comment: C0603C104K3RACTU)
C14  value 100pF  Voltage Rating: 50V  [FP-C0603C-CF-IPC_B]  (hidden comment: CC0603KRX7R9BB101)
C15  value 100pF  Voltage Rating: 50V  [FP-C0603C-CF-IPC_B]  (hidden comment: CC0603KRX7R9BB101)
C16  value 100pF  Voltage Rating: 50V  [FP-C0603C-CF-IPC_B]  (hidden comment: CC0603KRX7R9BB101)
C17  value 100pF  Voltage Rating: 50V  [FP-C0603C-CF-IPC_B]  (hidden comment: CC0603KRX7R9BB101)
C18  Voltage Rating: 25V  Capacitance: 0.10μF  [FP-C0603C-CF-IPC_B]  (hidden comment: C0603C104K3RACTU)
C70  value 100pF  Voltage Rating: 50V  [FP-C0603C-CF-IPC_B]  (hidden comment: CC0603KRX7R9BB101)
C71  value 100pF  Voltage Rating: 50V  [FP-C0603C-CF-IPC_B]  (hidden comment: CC0603KRX7R9BB101)
C72  value 100pF  Voltage Rating: 50V  [FP-C0603C-CF-IPC_B]  (hidden comment: CC0603KRX7R9BB101)
C73  value 100pF  Voltage Rating: 50V  [FP-C0603C-CF-IPC_B]  (hidden comment: CC0603KRX7R9BB101)
J1  Manufacturer: SULLINS  [FP-SBH11-PBPC-D08-ST-BK-MFG]  (hidden comment: SBH11-PBPC-D08-ST-BK)
J2  Manufacturer: SULLINS  [FP-SBH11-PBPC-D08-ST-BK-MFG]  (hidden comment: SBH11-PBPC-D08-ST-BK)
J3  Manufacturer: SULLINS  [FP-SBH11-PBPC-D08-ST-BK-MFG]  (hidden comment: SBH11-PBPC-D08-ST-BK)
J4  Manufacturer: SULLINS  [FP-SBH11-PBPC-D08-ST-BK-MFG]  (hidden comment: SBH11-PBPC-D08-ST-BK)
L1  value 1μH  [FP-MLZ2012-0_85-IPC_B]  (hidden comment: MLZ2012N1R0LT000)
L2  value 1μH  [FP-MLZ2012-0_85-IPC_B]  (hidden comment: MLZ2012N1R0LT000)
L3  value 1μH  [FP-MLZ2012-0_85-IPC_B]  (hidden comment: MLZ2012N1R0LT000)
L4  value 1μH  [FP-MLZ2012-0_85-IPC_B]  (hidden comment: MLZ2012N1R0LT000)
L5  value 1μH  [FP-MLZ2012-0_85-IPC_B]  (hidden comment: MLZ2012N1R0LT000)
L6  value 1μH  [FP-MLZ2012-0_85-IPC_B]  (hidden comment: MLZ2012N1R0LT000)
L7  value 1μH  [FP-MLZ2012-0_85-IPC_B]  (hidden comment: MLZ2012N1R0LT000)
L8  value 1μH  [FP-MLZ2012-0_85-IPC_B]  (hidden comment: MLZ2012N1R0LT000)
L9  value 1μH  [FP-MLZ2012-0_85-IPC_B]  (hidden comment: MLZ2012N1R0LT000)
L10  value 1μH  [FP-MLZ2012-0_85-IPC_B]  (hidden comment: MLZ2012N1R0LT000)
L11  value 1μH  [FP-MLZ2012-0_85-IPC_B]  (hidden comment: MLZ2012N1R0LT000)
L12  value 1μH  [FP-MLZ2012-0_85-IPC_B]  (hidden comment: MLZ2012N1R0LT000)
L13  value 1μH  [FP-MLZ2012-0_85-IPC_B]  (hidden comment: MLZ2012N1R0LT000)
L14  value 1μH  [FP-MLZ2012-0_85-IPC_B]  (hidden comment: MLZ2012N1R0LT000)
L15  value 1μH  [FP-MLZ2012-0_85-IPC_B]  (hidden comment: MLZ2012N1R0LT000)
L16  value 1μH  [FP-MLZ2012-0_85-IPC_B]  (hidden comment: MLZ2012N1R0LT000)
R1  value 100Ω  Power: 0.1W  [FP-AC0603-IPC_B]  (hidden comment: RMCF0603FT100R)
R2  value 100Ω  Power: 0.1W  [FP-AC0603-IPC_B]  (hidden comment: RMCF0603FT100R)
R3  value 100Ω  Power: 0.1W  [FP-AC0603-IPC_B]  (hidden comment: RMCF0603FT100R)
R4  value 15kΩ  Power: 0.1W  [FP-AC0603-IPC_B]  (hidden comment: RT0603BRE0715KL)
R5  value 15kΩ  Power: 0.1W  [FP-AC0603-IPC_B]  (hidden comment: RT0603BRE0715KL)
R6  value 100Ω  Power: 0.1W  [FP-AC0603-IPC_B]  (hidden comment: RMCF0603FT100R)
R7  value 100Ω  Power: 0.1W  [FP-AC0603-IPC_B]  (hidden comment: RMCF0603FT100R)
R8  value 100Ω  Power: 0.1W  [FP-AC0603-IPC_B]  (hidden comment: RMCF0603FT100R)
R9  value 15kΩ  Power: 0.1W  [FP-AC0603-IPC_B]  (hidden comment: RT0603BRE0715KL)
R10  value 15kΩ  Power: 0.1W  [FP-AC0603-IPC_B]  (hidden comment: RT0603BRE0715KL)
R11  value 100Ω  Power: 0.1W  [FP-AC0603-IPC_B]  (hidden comment: RMCF0603FT100R)
R12  value 100Ω  Power: 0.1W  [FP-AC0603-IPC_B]  (hidden comment: RMCF0603FT100R)
R13  value 15kΩ  Power: 0.1W  [FP-AC0603-IPC_B]  (hidden comment: RT0603BRE0715KL)
R14  value 15kΩ  Power: 0.1W  [FP-AC0603-IPC_B]  (hidden comment: RT0603BRE0715KL)
R15  value 15kΩ  Power: 0.1W  [FP-AC0603-IPC_B]  (hidden comment: RT0603BRE0715KL)
R16  value 120Ω  [FP-AC0603-IPC_B]  (hidden comment: RC0603FR-07120RL)
R17  value 120Ω  [FP-AC0603-IPC_B]  (hidden comment: RC0603FR-07120RL)
R18  value 120Ω  [FP-AC0603-IPC_B]  (hidden comment: RC0603FR-07120RL)
R19  value 120Ω  [FP-AC0603-IPC_B]  (hidden comment: RC0603FR-07120RL)
R20  value 15kΩ  Power: 0.1W  [FP-AC0603-IPC_B]  (hidden comment: RT0603BRE0715KL)
R83  value 120Ω  [FP-AC0603-IPC_B]  (hidden comment: RC0603FR-07120RL)
R84  value 120Ω  [FP-AC0603-IPC_B]  (hidden comment: RC0603FR-07120RL)
R85  value 120Ω  [FP-AC0603-IPC_B]  (hidden comment: RC0603FR-07120RL)
R86  value 120Ω  [FP-AC0603-IPC_B]  (hidden comment: RC0603FR-07120RL)
U2  Manufacturer: TEXAS INSTRUMENTS  [PW0016A_M]  (hidden comment: AM26LV32EIPWR)
U3  Manufacturer: TEXAS INSTRUMENTS  [PW0020A_L]  (hidden comment: SN74LV541ATPWR)
U4  Manufacturer: TEXAS INSTRUMENTS  [PW0016A_M]  (hidden comment: AM26LV32EIPWR)
U5  Manufacturer: TEXAS INSTRUMENTS  [PW0020A_L]  (hidden comment: SN74LV541ATPWR)
U6  Manufacturer: TEXAS INSTRUMENTS  [PW0016A_M]  (hidden comment: AM26LV31EIPWR)
U7  Manufacturer: TEXAS INSTRUMENTS  [PW0016A_M]  (hidden comment: AM26LV31EIPWR)

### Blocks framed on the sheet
DIFFERENTIAL TRANSCEIVERS: C13-C18 C70-C73 R13-R20 R83-R86 U6 U7
IC RECEIVER: C2 C8 R4 R5 R9 R10 U2 U4
FILTER: C1 C3-C5 C7 C9-C11 L1-L16 R1-R3 R6-R8 R11 R12
BUFFER: C6 C12 U3 U5
GATE DRIVER CONNECTIONS: J1-J4

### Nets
+3.3V: C2.1 C6.1 C8.1 C12.1 C13.1 C18.1 R4.2 R9.2 R14.2 R20.2 U2.16(VCC) U3.20(VCC) U4.16(VCC) U5.20(VCC) U6.16(VCC) U7.16(VCC)
+12V: J1.1 J2.1 J3.1 J4.1
GND: C2.2 C6.2 C8.2 C12.2 C13.2 C14.2 C15.2 C16.2 C17.2 C18.2 C70.2 C71.2 C72.2 C73.2 J1.2 J1.12 J1.14 J1.16 J2.2 J2.12 J2.14 J2.16 J3.2 J3.12 J3.14 J3.16 J4.2 J4.12 J4.14 J4.16 R5.1 R10.1 R13.1 R15.1 U2.8(GND) U3.1(~{OE1}) U3.2(A1) U3.3(A2) U3.10(GND) U3.19(~{OE2}) U4.8(GND) U5.1(~{OE1}) U5.2(A1) U5.3(A2) U5.10(GND) U5.19(~{OE2}) U6.8(GND) U7.8(GND)
INA_FLT: U4.3(1Y) ; off-sheet INA_FLT
INA_FLT_N: J4.8 L9.1
INA_FLT_N_FILT: C7.2 L9.2 R7.1 U4.1(1B)
INA_FLT_P: J4.7 L10.1
INA_FLT_P_FILT: C7.1 L10.2 R7.2 U4.2(1A)
INA_HS: R19.1 ; off-sheet INA_HS
INA_HS_N: J4.4 U7.3(1Z)
INA_HS_P: J4.3 U7.2(1Y)
INA_LEN: J4.13 U5.15(Y4)
INA_LEN_CTRL: U5.5(A4) ; off-sheet INA_LEN_CTRL
INA_LS: R18.1 ; off-sheet INA_LS
INA_LS_N: J4.6 U7.5(2Z)
INA_LS_P: J4.5 U7.6(2Y)
INA_NTC: U4.13(4Y) ; off-sheet INA_NTC
INA_NTC_N: J4.10 L11.1
INA_NTC_N_FILT: C9.2 L11.2 R8.1 U4.15(4B)
INA_NTC_P: J4.9 L12.1
INA_NTC_P_FILT: C9.1 L12.2 R8.2 U4.14(4A)
INA_OCEN: J4.15 U5.14(Y5)
INA_OCEN_CTRL: U5.6(A5) ; off-sheet INA_OCEN_CTRL
INA_PSDIS: J4.11 U5.16(Y3)
INA_PSDIS_CTRL: U5.4(A3) ; off-sheet INA_PSDIS_CTRL
INB_FLT: U4.11(3Y) ; off-sheet INB_FLT
INB_FLT_N: J3.8 L14.1
INB_FLT_N_FILT: C10.2 L14.2 R11.1 U4.9(3B)
INB_FLT_P: J3.7 L13.1
INB_FLT_P_FILT: C10.1 L13.2 R11.2 U4.10(3A)
INB_HS: R17.1 ; off-sheet INB_HS
INB_HS_N: J3.4 U7.11(3Z)
INB_HS_P: J3.3 U7.10(3Y)
INB_LEN: J3.13 U5.12(Y7)
INB_LEN_CTRL: U5.8(A7) ; off-sheet INB_LEN_CTRL
INB_LS: R16.1 ; off-sheet INB_LS
INB_LS_N: J3.6 U7.13(4Z)
INB_LS_P: J3.5 U7.14(4Y)
INB_NTC: U4.5(2Y) ; off-sheet INB_NTC
INB_NTC_N: J3.10 L16.1
INB_NTC_N_FILT: C11.2 L16.2 R12.1 U4.7(2B)
INB_NTC_P: J3.9 L15.1
INB_NTC_P_FILT: C11.1 L15.2 R12.2 U4.6(2A)
INB_OCEN: J3.15 U5.11(Y8)
INB_OCEN_CTRL: U5.9(A8) ; off-sheet INB_OCEN_CTRL
INB_PSDIS: J3.11 U5.13(Y6)
INB_PSDIS_CTRL: U5.7(A6) ; off-sheet INB_PSDIS_CTRL
OUTA_FLT: U2.3(1Y) ; off-sheet OUTA_FLT
OUTA_FLT_N: J2.8 L1.1
OUTA_FLT_N_FILT: C1.2 L1.2 R1.1 U2.1(1B)
OUTA_FLT_P: J2.7 L2.1
OUTA_FLT_P_FILT: C1.1 L2.2 R1.2 U2.2(1A)
OUTA_HS: R83.1 ; off-sheet OUTA_HS
OUTA_HS_N: J2.4 U6.3(1Z)
OUTA_HS_P: J2.3 U6.2(1Y)
OUTA_LEN: J2.13 U3.15(Y4)
OUTA_LEN_CTRL: U3.5(A4) ; off-sheet OUTA_LEN_CTRL
OUTA_LS: R84.1 ; off-sheet OUTA_LS
OUTA_LS_N: J2.6 U6.5(2Z)
OUTA_LS_P: J2.5 U6.6(2Y)
OUTA_NTC: U2.13(4Y) ; off-sheet OUTA_NTC
OUTA_NTC_N: J2.10 L3.1
OUTA_NTC_N_FILT: C3.2 L3.2 R2.1 U2.15(4B)
OUTA_NTC_P: J2.9 L4.1
OUTA_NTC_P_FILT: C3.1 L4.2 R2.2 U2.14(4A)
OUTA_OCEN: J2.15 U3.14(Y5)
OUTA_OCEN_CTRL: U3.6(A5) ; off-sheet OUTA_OCEN_CTRL
OUTA_PSDIS: J2.11 U3.16(Y3)
OUTA_PSDIS_CTRL: U3.4(A3) ; off-sheet OUTA_PSDIS_CTRL
OUTB_FLT: U2.11(3Y) ; off-sheet OUTB_FLT
OUTB_FLT_N: J1.8 L6.1
OUTB_FLT_N_FILT: C4.2 L6.2 R3.1 U2.9(3B)
OUTB_FLT_P: J1.7 L5.1
OUTB_FLT_P_FILT: C4.1 L5.2 R3.2 U2.10(3A)
OUTB_HS: R85.1 ; off-sheet OUTB_HS
OUTB_HS_N: J1.4 U6.11(3Z)
OUTB_HS_P: J1.3 U6.10(3Y)
OUTB_LEN: J1.13 U3.12(Y7)
OUTB_LEN_CTRL: U3.8(A7) ; off-sheet OUTB_LEN_CTRL
OUTB_LS: R86.1 ; off-sheet OUTB_LS
OUTB_LS_N: J1.6 U6.13(4Z)
OUTB_LS_P: J1.5 U6.14(4Y)
OUTB_NTC: U2.5(2Y) ; off-sheet OUTB_NTC
OUTB_NTC_N: J1.10 L8.1
OUTB_NTC_N_FILT: C5.2 L8.2 R6.1 U2.7(2B)
OUTB_NTC_P: J1.9 L7.1
OUTB_NTC_P_FILT: C5.1 L7.2 R6.2 U2.6(2A)
OUTB_OCEN: J1.15 U3.11(Y8)
OUTB_OCEN_CTRL: U3.9(A8) ; off-sheet OUTB_OCEN_CTRL
OUTB_PSDIS: J1.11 U3.13(Y6)
OUTB_PSDIS_CTRL: U3.7(A6) ; off-sheet OUTB_PSDIS_CTRL
NetC14_1: C14.1 R86.2 U6.15(4A)
NetC15_1: C15.1 R85.2 U6.9(3A)
NetC16_1: C16.1 R84.2 U6.7(2A)
NetC17_1: C17.1 R83.2 U6.1(1A)
NetC70_1: C70.1 R19.2 U7.1(1A)
NetC71_1: C71.1 R18.2 U7.7(2A)
NetC72_1: C72.1 R17.2 U7.9(3A)
NetC73_1: C73.1 R16.2 U7.15(4A)
NetR4_1: R4.1 U2.4(G)
NetR5_2: R5.2 U2.12(~{G})
NetR9_1: R9.1 U4.4(G)
NetR10_2: R10.2 U4.12(~{G})
NetR13_2: R13.2 U6.12(~{G})
NetR14_1: R14.1 U6.4(G)
NetR15_2: R15.2 U7.12(~{G})
NetR20_1: R20.1 U7.4(G)

Not connected (* = marked no-connect by the designer): U3 17(Y2) 18(Y1); U5 17(Y2) 18(Y1)

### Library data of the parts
C1 C3-C5 C7 C9-C11 = CMP-03020-017376-1: CAP CER 27PF 250V C0G/NP0 0603; Manufacturer: KEMET; Tolerance: 0.01; Temperature Characteristic: C0G; Material: Ceramic; Temperature Coefficient: 30ppm/°C
C2 C6 C8 C12 C13 C18 = CMP-2006-03057-2: as C54 on sheet Controller
C14-C17 C70-C73 = CMP-001-00096-9: as C42 on sheet Voltage Sense
J1-J4 = SBH11-PBPC-D08-ST-BK: CONN HEADER VERT 16POS 2.54MM; Number of Positions: 16; Mated Stacking Heights: 18.35mm
L1-L16 = CMP-08253-000143-1: FIXED IND 1UH 1.15A 60 MOHM SMD; Manufacturer: TDK; Shielding: Shielded; Core Material: Ferrite; Self Resonant Frequency: 160MHz; Saturation Current: 220mA; Test Frequency: 2MHz; DC Resistance (DCR): 78mR; Tolerance: 20%
R1-R3 R6-R8 R11 R12 = CMP-009-00005-4: RES 100 OHM 1% 1/10W 0603; Manufacturer: YAGEO; Manufacturer Part Number: RC0603FR-13100RL; Voltage Rating: 75V
R4 R5 R9 R10 R13-R15 R20 = CMP-009-00107-4: RES SMD 15K OHM 0.1% 1/10W 0603; Manufacturer: YAGEO; Voltage Rating: 75V
R16-R19 R83-R86 = CMP-009-00006-5: RES 120 OHM 1% 1/10W 0603; Manufacturer: YAGEO; Voltage Rating: 75V; Power: 0.1W
U2 U4 = CMP-0310-00537-3: IC RECEIVER 0/4 16TSSOP; Supply Voltage(s)(Min)(V): 3; Supply Voltage(s)(Max)(V): 3.6; Receivers Per Package: 4; SubFamily: RS-422; Eco-Plan: Green (RoHS & no Sb/Br); ESD(kV): 15; Supply Voltage(s)(V): 3.3; # of TX/RX: 0 TX / 4 RX; Rating: Catalog
U3 U5 = CMP-0440-01163-3: IC BUF NON-INVERT 5.5V 20TSSOP; Bits(#): 8; Voltage(Nom)(V): 5; ICC @ Nom Voltage(Max)(mA): 0.02; VCC(Max)(V): 5.5; Output Type: CMOS; Rating: Catalog; Input Type: TTL; VCC(Min)(V): 4.5; F @ Nom Voltage(Max)(Mhz): 110; tpd @ Nom Voltage(Max)(ns): 7.9
U6 U7 = CMP-0310-00542-2: Eco-Plan: Green (RoHS & no Sb/Br); Rating: Catalog; Supply Voltage(s)(Max)(V): 3.6; ICC(Max)(mA): 0.1; Drivers Per Package: 4; ESD(kV): 15; # of TX/RX: 4 TX / 0 RX; SubFamily: RS-422; Supply Voltage(s)(V): 3.3; Supply Voltage(s)(Min)(V): 3

## Sheet Current Sense.SchDoc: 60KW GMA DAB (CONTROL) - CURRENT SENSE
size 431 x 279 mm; Date: 11/2023; Revision: 1.0; SheetNumber: 4; SheetTotal: 5; SheetSize: B; DrawingNumber: CRD60DD12N-GMA-CONTROL
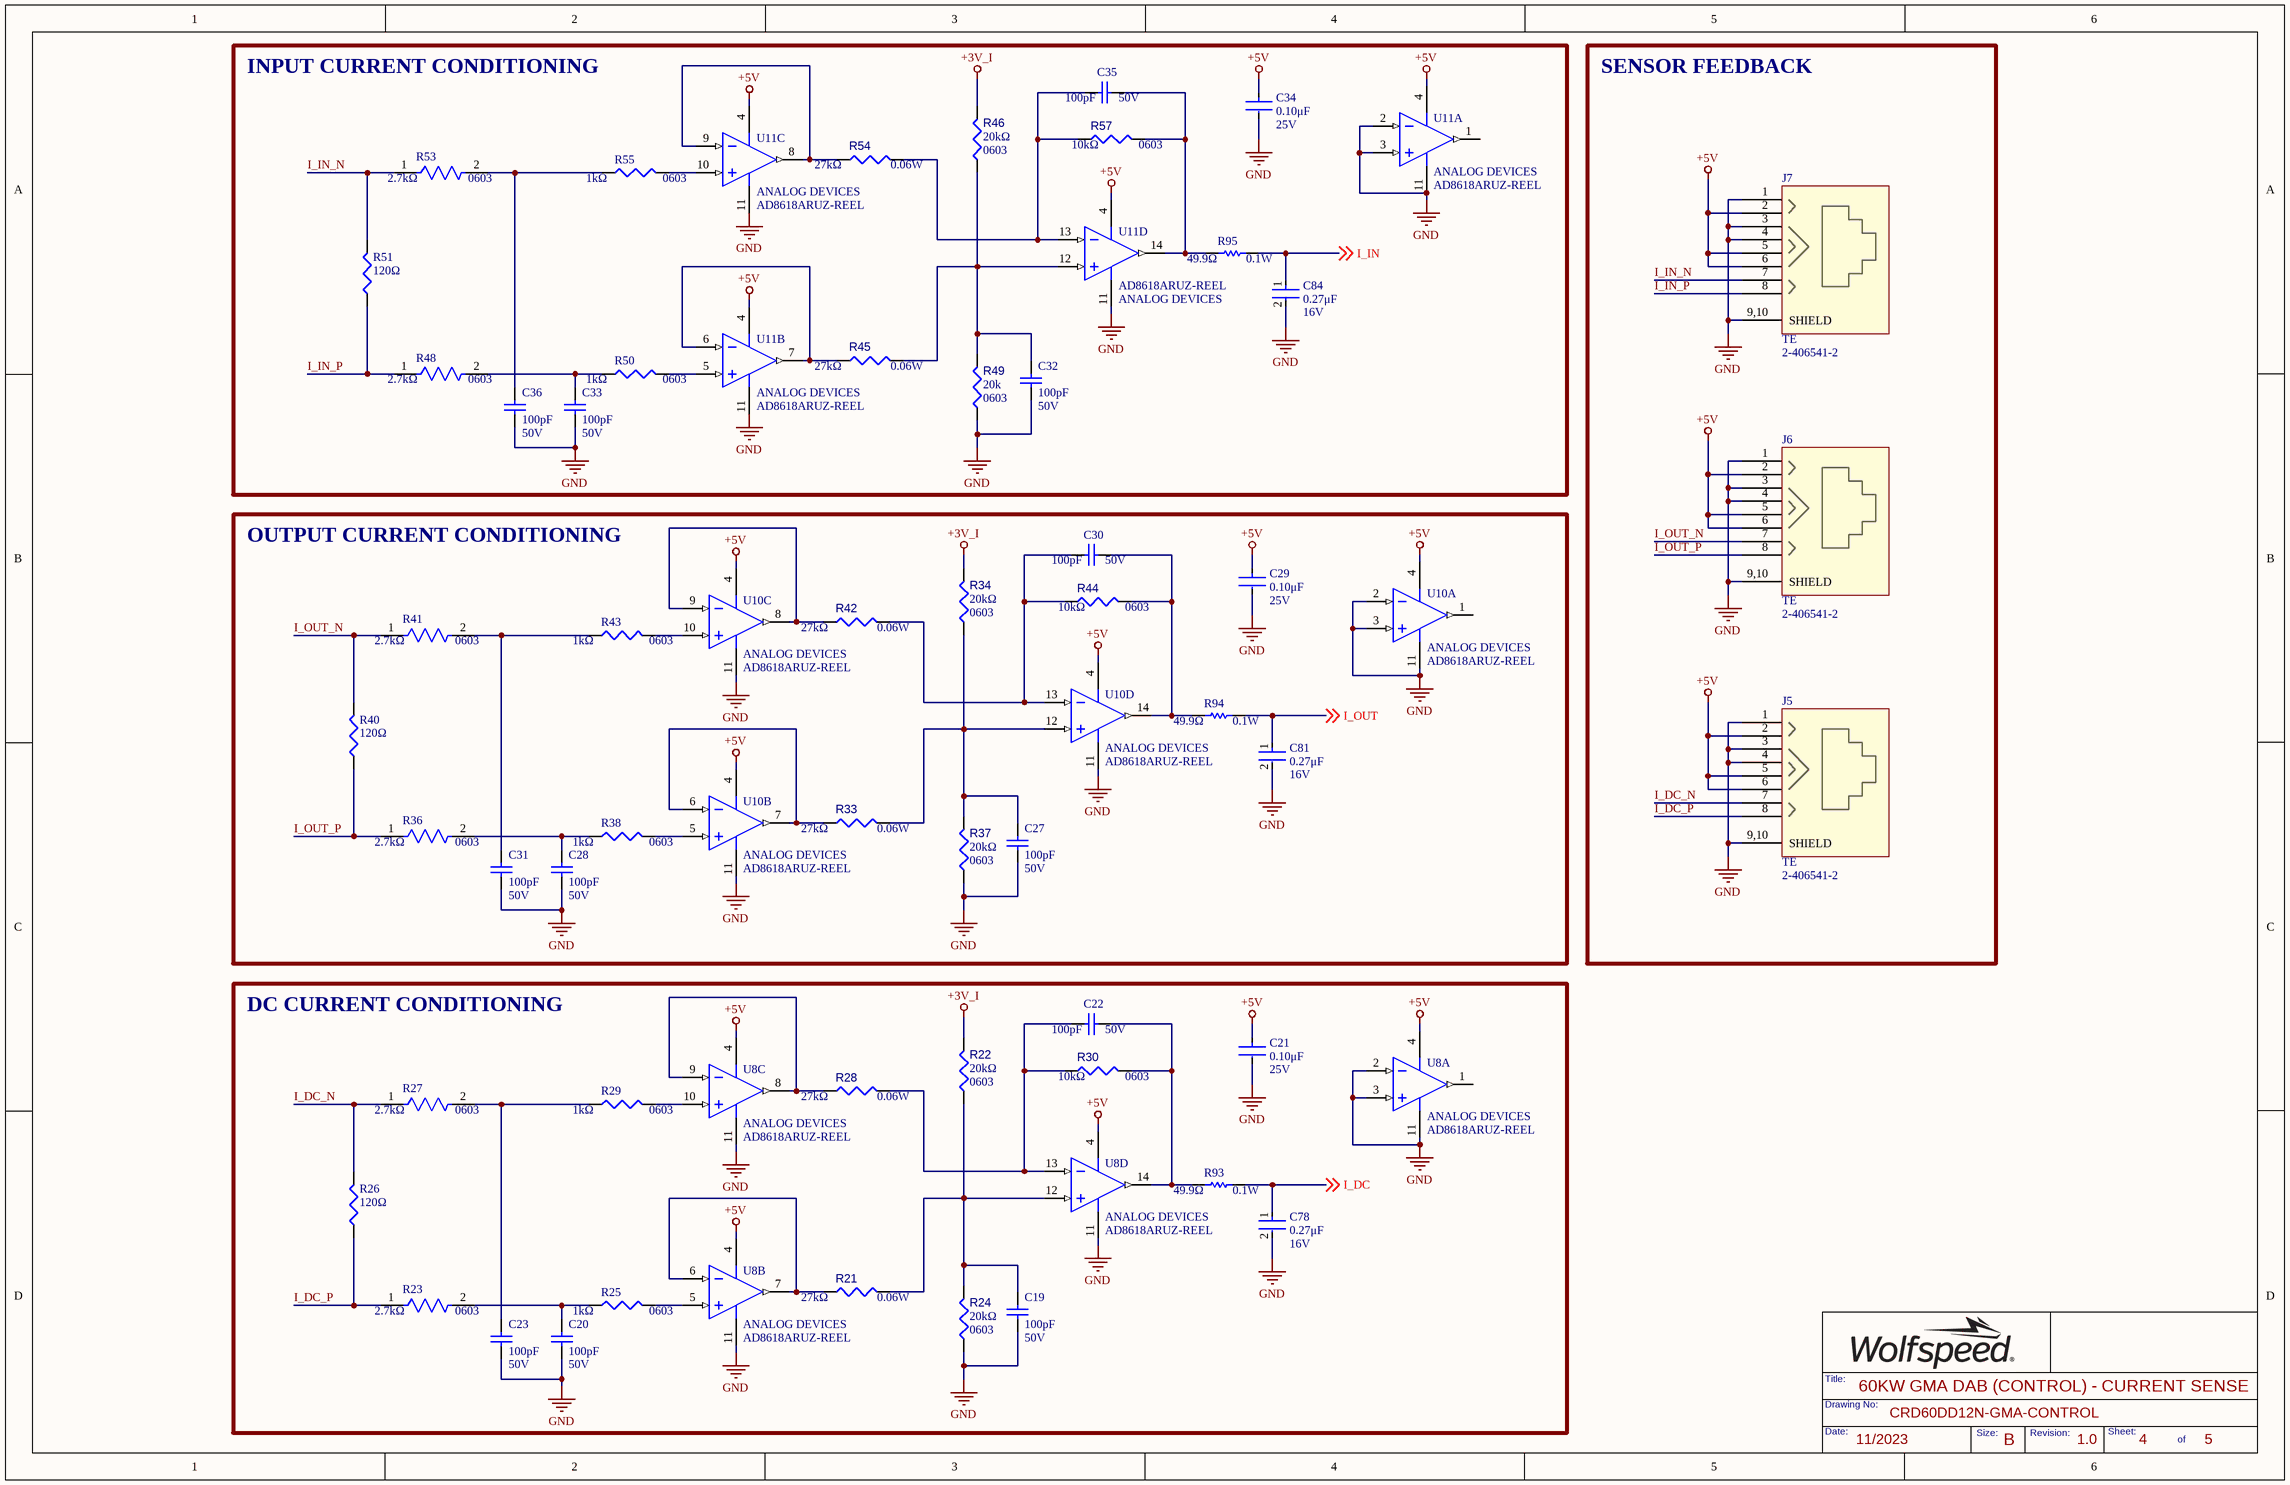
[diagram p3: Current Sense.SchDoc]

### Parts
C19  value 100pF  Voltage Rating: 50V  [FP-C0603C-CF-IPC_B]  (hidden comment: CC0603KRX7R9BB101)
C20  value 100pF  Voltage Rating: 50V  [FP-C0603C-CF-IPC_B]  (hidden comment: CC0603KRX7R9BB101)
C21  Voltage Rating: 25V  Capacitance: 0.10μF  [FP-C0603C-CF-IPC_B]  (hidden comment: C0603C104K3RACTU)
C22  value 100pF  Voltage Rating: 50V  [FP-C0603C-CF-IPC_B]  (hidden comment: CC0603KRX7R9BB101)
C23  value 100pF  Voltage Rating: 50V  [FP-C0603C-CF-IPC_B]  (hidden comment: CC0603KRX7R9BB101)
C27  value 100pF  Voltage Rating: 50V  [FP-C0603C-CF-IPC_B]  (hidden comment: CC0603KRX7R9BB101)
C28  value 100pF  Voltage Rating: 50V  [FP-C0603C-CF-IPC_B]  (hidden comment: CC0603KRX7R9BB101)
C29  Voltage Rating: 25V  Capacitance: 0.10μF  [FP-C0603C-CF-IPC_B]  (hidden comment: C0603C104K3RACTU)
C30  value 100pF  Voltage Rating: 50V  [FP-C0603C-CF-IPC_B]  (hidden comment: CC0603KRX7R9BB101)
C31  value 100pF  Voltage Rating: 50V  [FP-C0603C-CF-IPC_B]  (hidden comment: CC0603KRX7R9BB101)
C32  value 100pF  Voltage Rating: 50V  [FP-C0603C-CF-IPC_B]  (hidden comment: CC0603KRX7R9BB101)
C33  value 100pF  Voltage Rating: 50V  [FP-C0603C-CF-IPC_B]  (hidden comment: CC0603KRX7R9BB101)
C34  Voltage Rating: 25V  Capacitance: 0.10μF  [FP-C0603C-CF-IPC_B]  (hidden comment: C0603C104K3RACTU)
C35  value 100pF  Voltage Rating: 50V  [FP-C0603C-CF-IPC_B]  (hidden comment: CC0603KRX7R9BB101)
C36  value 100pF  Voltage Rating: 50V  [FP-C0603C-CF-IPC_B]  (hidden comment: CC0603KRX7R9BB101)
C78  Voltage Rating (DC): 16V  Capacitance: 0.27μF  [FP-GCM188-0_1-IPC_A]  (hidden comment: GCM188R71C274KA37D)
C81  Voltage Rating (DC): 16V  Capacitance: 0.27μF  [FP-GCM188-0_1-IPC_A]  (hidden comment: GCM188R71C274KA37D)
C84  Voltage Rating (DC): 16V  Capacitance: 0.27μF  [FP-GCM188-0_1-IPC_A]  (hidden comment: GCM188R71C274KA37D)
J5  Manufacturer: TE  [2-406541-2]  (hidden comment: 2-406541-2)
J6  Manufacturer: TE  [2-406541-2]  (hidden comment: 2-406541-2)
J7  Manufacturer: TE  [2-406541-2]  (hidden comment: 2-406541-2)
R21  value 27kΩ  Power: 0.06W  [FP-AC0603-IPC_B]  (hidden comment: RR0816P-273-D)
R22  value 20kΩ  Case/Package: 0603  [FP-AC0603-IPC_B]  (hidden comment: RMCF0603FT20K0)
R23  value 2.7kΩ  Size Code: 0603  [FP-RR0816-IPC_C]  (hidden comment: RR0816P-272-D)
R24  value 20kΩ  Case/Package: 0603  [FP-AC0603-IPC_B]  (hidden comment: RMCF0603FT20K0)
R25  value 1kΩ  Case/Package: 0603  [R0603_MD]  (hidden comment: ERA-3ARW102V)
R26  value 120Ω  [FP-AC0603-IPC_B]  (hidden comment: RC0603FR-07120RL)
R27  value 2.7kΩ  Size Code: 0603  [FP-RR0816-IPC_C]  (hidden comment: RR0816P-272-D)
R28  value 27kΩ  Power: 0.06W  [FP-AC0603-IPC_B]  (hidden comment: RR0816P-273-D)
R29  value 1kΩ  Case/Package: 0603  [R0603_MD]  (hidden comment: ERA-3ARW102V)
R30  value 10kΩ  Case/Package: 0603  [FP-AC0603-IPC_B]  (hidden comment: RG1608P-103-BT5)
R33  value 27kΩ  Power: 0.06W  [FP-AC0603-IPC_B]  (hidden comment: RR0816P-273-D)
R34  value 20kΩ  Case/Package: 0603  [FP-AC0603-IPC_B]  (hidden comment: RMCF0603FT20K0)
R36  value 2.7kΩ  Size Code: 0603  [FP-RR0816-IPC_C]  (hidden comment: RR0816P-272-D)
R37  value 20kΩ  Case/Package: 0603  [FP-AC0603-IPC_B]  (hidden comment: RMCF0603FT20K0)
R38  value 1kΩ  Case/Package: 0603  [R0603_MD]  (hidden comment: ERA-3ARW102V)
R40  value 120Ω  [FP-AC0603-IPC_B]  (hidden comment: RC0603FR-07120RL)
R41  value 2.7kΩ  Size Code: 0603  [FP-RR0816-IPC_C]  (hidden comment: RR0816P-272-D)
R42  value 27kΩ  Power: 0.06W  [FP-AC0603-IPC_B]  (hidden comment: RR0816P-273-D)
R43  value 1kΩ  Case/Package: 0603  [R0603_MD]  (hidden comment: ERA-3ARW102V)
R44  value 10kΩ  Case/Package: 0603  [FP-AC0603-IPC_B]  (hidden comment: RG1608P-103-BT5)
R45  value 27kΩ  Power: 0.06W  [FP-AC0603-IPC_B]  (hidden comment: RR0816P-273-D)
R46  value 20kΩ  Case/Package: 0603  [FP-AC0603-IPC_B]  (hidden comment: RMCF0603FT20K0)
R48  value 2.7kΩ  Size Code: 0603  [FP-RR0816-IPC_C]  (hidden comment: RR0816P-272-D)
R49  value 20k  Case/Package: 0603  [FP-AC0603-IPC_B]  (hidden comment: RMCF0603FT20K0)
R50  value 1kΩ  Case/Package: 0603  [R0603_MD]  (hidden comment: ERA-3ARW102V)
R51  value 120Ω  [FP-AC0603-IPC_B]  (hidden comment: RC0603FR-07120RL)
R53  value 2.7kΩ  Size Code: 0603  [FP-RR0816-IPC_C]  (hidden comment: RR0816P-272-D)
R54  value 27kΩ  Power: 0.06W  [FP-AC0603-IPC_B]  (hidden comment: RR0816P-273-D)
R55  value 1kΩ  Case/Package: 0603  [R0603_MD]  (hidden comment: ERA-3ARW102V)
R57  value 10kΩ  Case/Package: 0603  [FP-AC0603-IPC_B]  (hidden comment: RG1608P-103-BT5)
R93  Resistance: 49.9Ω  Power Rating: 0.1W  [FP-MCR03-IPC_B]  (hidden comment: ERJ-3EKF49R9V)
R94  Resistance: 49.9Ω  Power Rating: 0.1W  [FP-MCR03-IPC_B]  (hidden comment: ERJ-3EKF49R9V)
R95  Resistance: 49.9Ω  Power Rating: 0.1W  [FP-MCR03-IPC_B]  (hidden comment: ERJ-3EKF49R9V)
U8  AD8618ARUZ-REEL  Manufacturer: ANALOG DEVICES  [ADI-RU-14_L]  (parts A,B,C,D of 4)
U10  AD8618ARUZ-REEL  Manufacturer: ANALOG DEVICES  [ADI-RU-14_L]  (parts A,B,C,D of 4)
U11  AD8618ARUZ-REEL  Manufacturer: ANALOG DEVICES  [ADI-RU-14_L]  (parts A,B,C,D of 4)

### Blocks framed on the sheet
INPUT CURRENT CONDITIONING: C32-C36 C84 R45 R46 R48-R51 R53-R55 R57 R95 U11
SENSOR FEEDBACK: J5-J7
OUTPUT CURRENT CONDITIONING: C27-C31 C81 R33 R34 R36-R38 R40-R44 R94 U10
DC CURRENT CONDITIONING: C19-C23 C78 R21-R30 R93 U8

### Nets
+3V_I: R22.2 R34.2 R46.2
+5V: C21.1 C29.1 C34.1 J5.2 J5.5 J5.6 J6.2 J6.5 J6.6 J7.2 J7.5 J7.6 U8.4(+V) U10.4(+V) U11.4(+V)
GND: C19.2 C20.2 C21.2 C23.2 C27.2 C28.2 C29.2 C31.2 C32.2 C33.2 C34.2 C36.2 C78.2 C81.2 C84.2 J5.1 J5.3 J5.4 J5.9,10(SHIELD) J6.1 J6.3 J6.4 J6.9,10(SHIELD) J7.1 J7.3 J7.4 J7.9,10(SHIELD) R24.1 R37.1 R49.1 U8.2(-IN_A) U8.3(+IN_A) U8.11(-V) U10.2(-IN_A) U10.3(+IN_A) U10.11(-V) U11.2(-IN_A) U11.3(+IN_A) U11.11(-V)
I_DC: C78.1 R93.2 ; off-sheet I_DC
I_DC_N: J5.7 R26.2 R27.1
I_DC_P: J5.8 R23.1 R26.1
I_IN: C84.1 R95.2 ; off-sheet I_IN
I_IN_N: J7.7 R51.2 R53.1
I_IN_P: J7.8 R48.1 R51.1
I_OUT: C81.1 R94.2 ; off-sheet I_OUT
I_OUT_N: J6.7 R40.2 R41.1
I_OUT_P: J6.8 R36.1 R40.1
NetC19_1: C19.1 R21.2 R22.1 R24.2 U8.12(+IN_D)
NetC20_1: C20.1 R23.2 R25.1
NetC22_1: C22.1 R28.2 R30.1 U8.13(-IN_D)
NetC22_2: C22.2 R30.2 R93.1 U8.14(OUT_D)
NetC23_1: C23.1 R27.2 R29.1
NetC27_1: C27.1 R33.2 R34.1 R37.2 U10.12(+IN_D)
NetC28_1: C28.1 R36.2 R38.1
NetC30_1: C30.1 R42.2 R44.1 U10.13(-IN_D)
NetC30_2: C30.2 R44.2 R94.1 U10.14(OUT_D)
NetC31_1: C31.1 R41.2 R43.1
NetC32_1: C32.1 R45.2 R46.1 R49.2 U11.12(+IN_D)
NetC33_1: C33.1 R48.2 R50.1
NetC35_1: C35.1 R54.2 R57.1 U11.13(-IN_D)
NetC35_2: C35.2 R57.2 R95.1 U11.14(OUT_D)
NetC36_1: C36.1 R53.2 R55.1
NetR21_1: R21.1 U8.6(-IN_B) U8.7(OUT_B)
NetR25_2: R25.2 U8.5(+IN_B)
NetR28_1: R28.1 U8.8(OUT_C) U8.9(-IN_C)
NetR29_2: R29.2 U8.10(+IN_C)
NetR33_1: R33.1 U10.6(-IN_B) U10.7(OUT_B)
NetR38_2: R38.2 U10.5(+IN_B)
NetR42_1: R42.1 U10.8(OUT_C) U10.9(-IN_C)
NetR43_2: R43.2 U10.10(+IN_C)
NetR45_1: R45.1 U11.6(-IN_B) U11.7(OUT_B)
NetR50_2: R50.2 U11.5(+IN_B)
NetR54_1: R54.1 U11.8(OUT_C) U11.9(-IN_C)
NetR55_2: R55.2 U11.10(+IN_C)

Not connected (* = marked no-connect by the designer): U8 1(OUT_A); U10 1(OUT_A); U11 1(OUT_A)

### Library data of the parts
C19 C20 C22 C23 C27 C28 C30-C33 C35 C36 = CMP-001-00096-9: as C42 on sheet Voltage Sense
C21 C29 C34 = CMP-2006-03057-2: as C54 on sheet Controller
C78 C81 C84 = CMP-06035-043171-1: as C79 on sheet Voltage Sense
J5-J7 = 2-406541-2: CONN MOD JACK R/A 8P8C SHLD
R21 R28 R33 R42 R45 R54 = CMP-009-00218-2: RES SMD 27K OHM 0.5% 1/16W 0603; Voltage Rating: 75V; MFG: Susumu
R22 R24 R34 R37 R46 R49 = CMP-009-00039-5: RES 20K OHM 1% 1/10W 0603; Manufacturer: STACKPOLE; Voltage Rating: 75V; Power: 100mW
R23 R27 R36 R41 R48 R53 = CMP-2000-02579-2: RES SMD 2.7K OHM 0.5% 1/16W 0603; Manufacturer: SUSUMU; Power Rating: 62.5mW; Voltage Rating: 75V; Temperature Coefficient: 25ppm/°C; Max Power Dissipation: 63mW
R25 R29 R38 R43 R50 R55 = CMP-009-00255-1: RES SMD 1K OHM 0.05% 1/10W 0603; Temperature Coefficient: 10ppm/°C; Voltage Rating: 75V; MFG: Panasonic; Power: 100mW
R26 R40 R51 = CMP-009-00006-5: as R16 on sheet Gate Drivers
R30 R44 R57 = CMP-009-00206-2: RES SMD 10K OHM 0.1% 1/10W 0603; Manufacturer: SUSUMU; Manufacturer Part Number: RG1608P-103-B-T5; Power: 100mW; Voltage Rating: 75V
R93-R95 = ERJ-3EKF49R9V: as R31 on sheet Voltage Sense
U8 U10 U11 = CMP-0384-01836-1: IC CMOS 4 CIRCUIT 14TSSOP; Generic Part Number: AD8618; Slew Rate: 12V/us; Amplifiers Per Package: 4; V Span Min: 2.7V; Input Offset Voltage: 23uV; V Span Max: 6V; Iq/Amp: 2mA; Small Signal Bandwidth: 24MHz; Input Bias Current: 200fA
